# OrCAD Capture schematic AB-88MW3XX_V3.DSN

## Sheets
1 01 TITLE, TOC: title: AB-88MW3XX V3.0; rev: 1; note: MV-SRxxxxx-xx
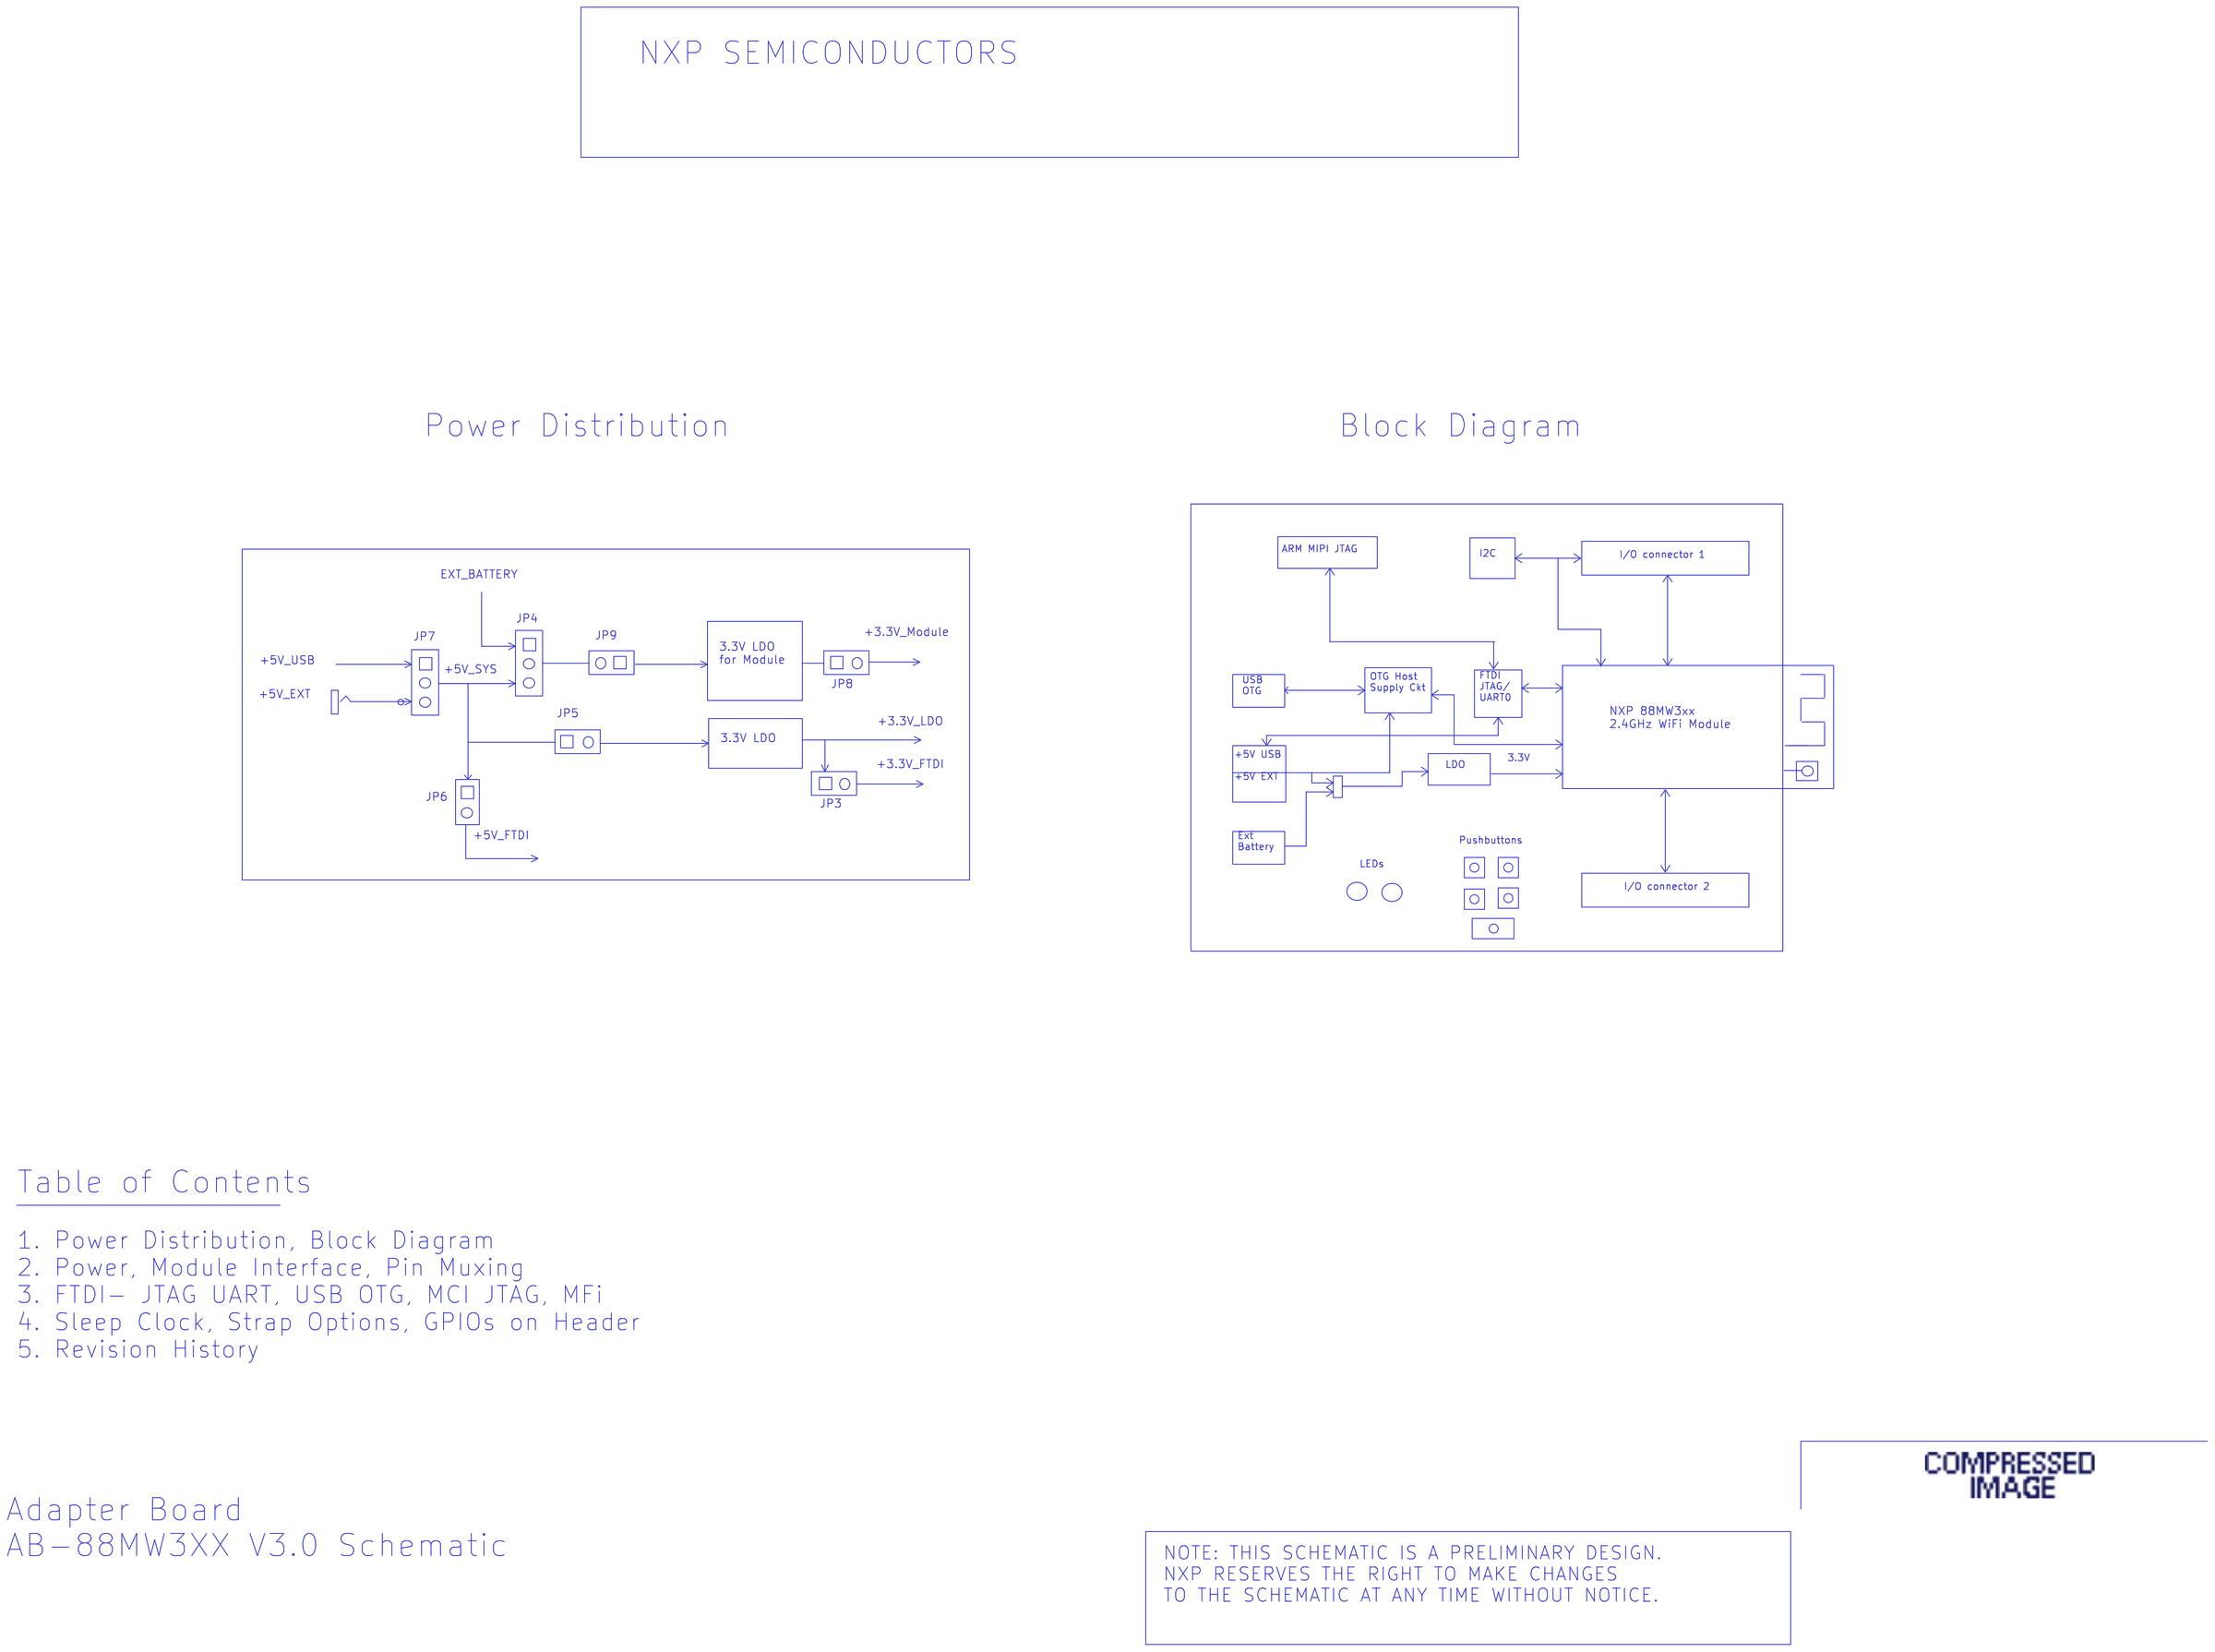
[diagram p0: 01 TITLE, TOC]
2 02 POWER, MODULE INTERFACE: size C
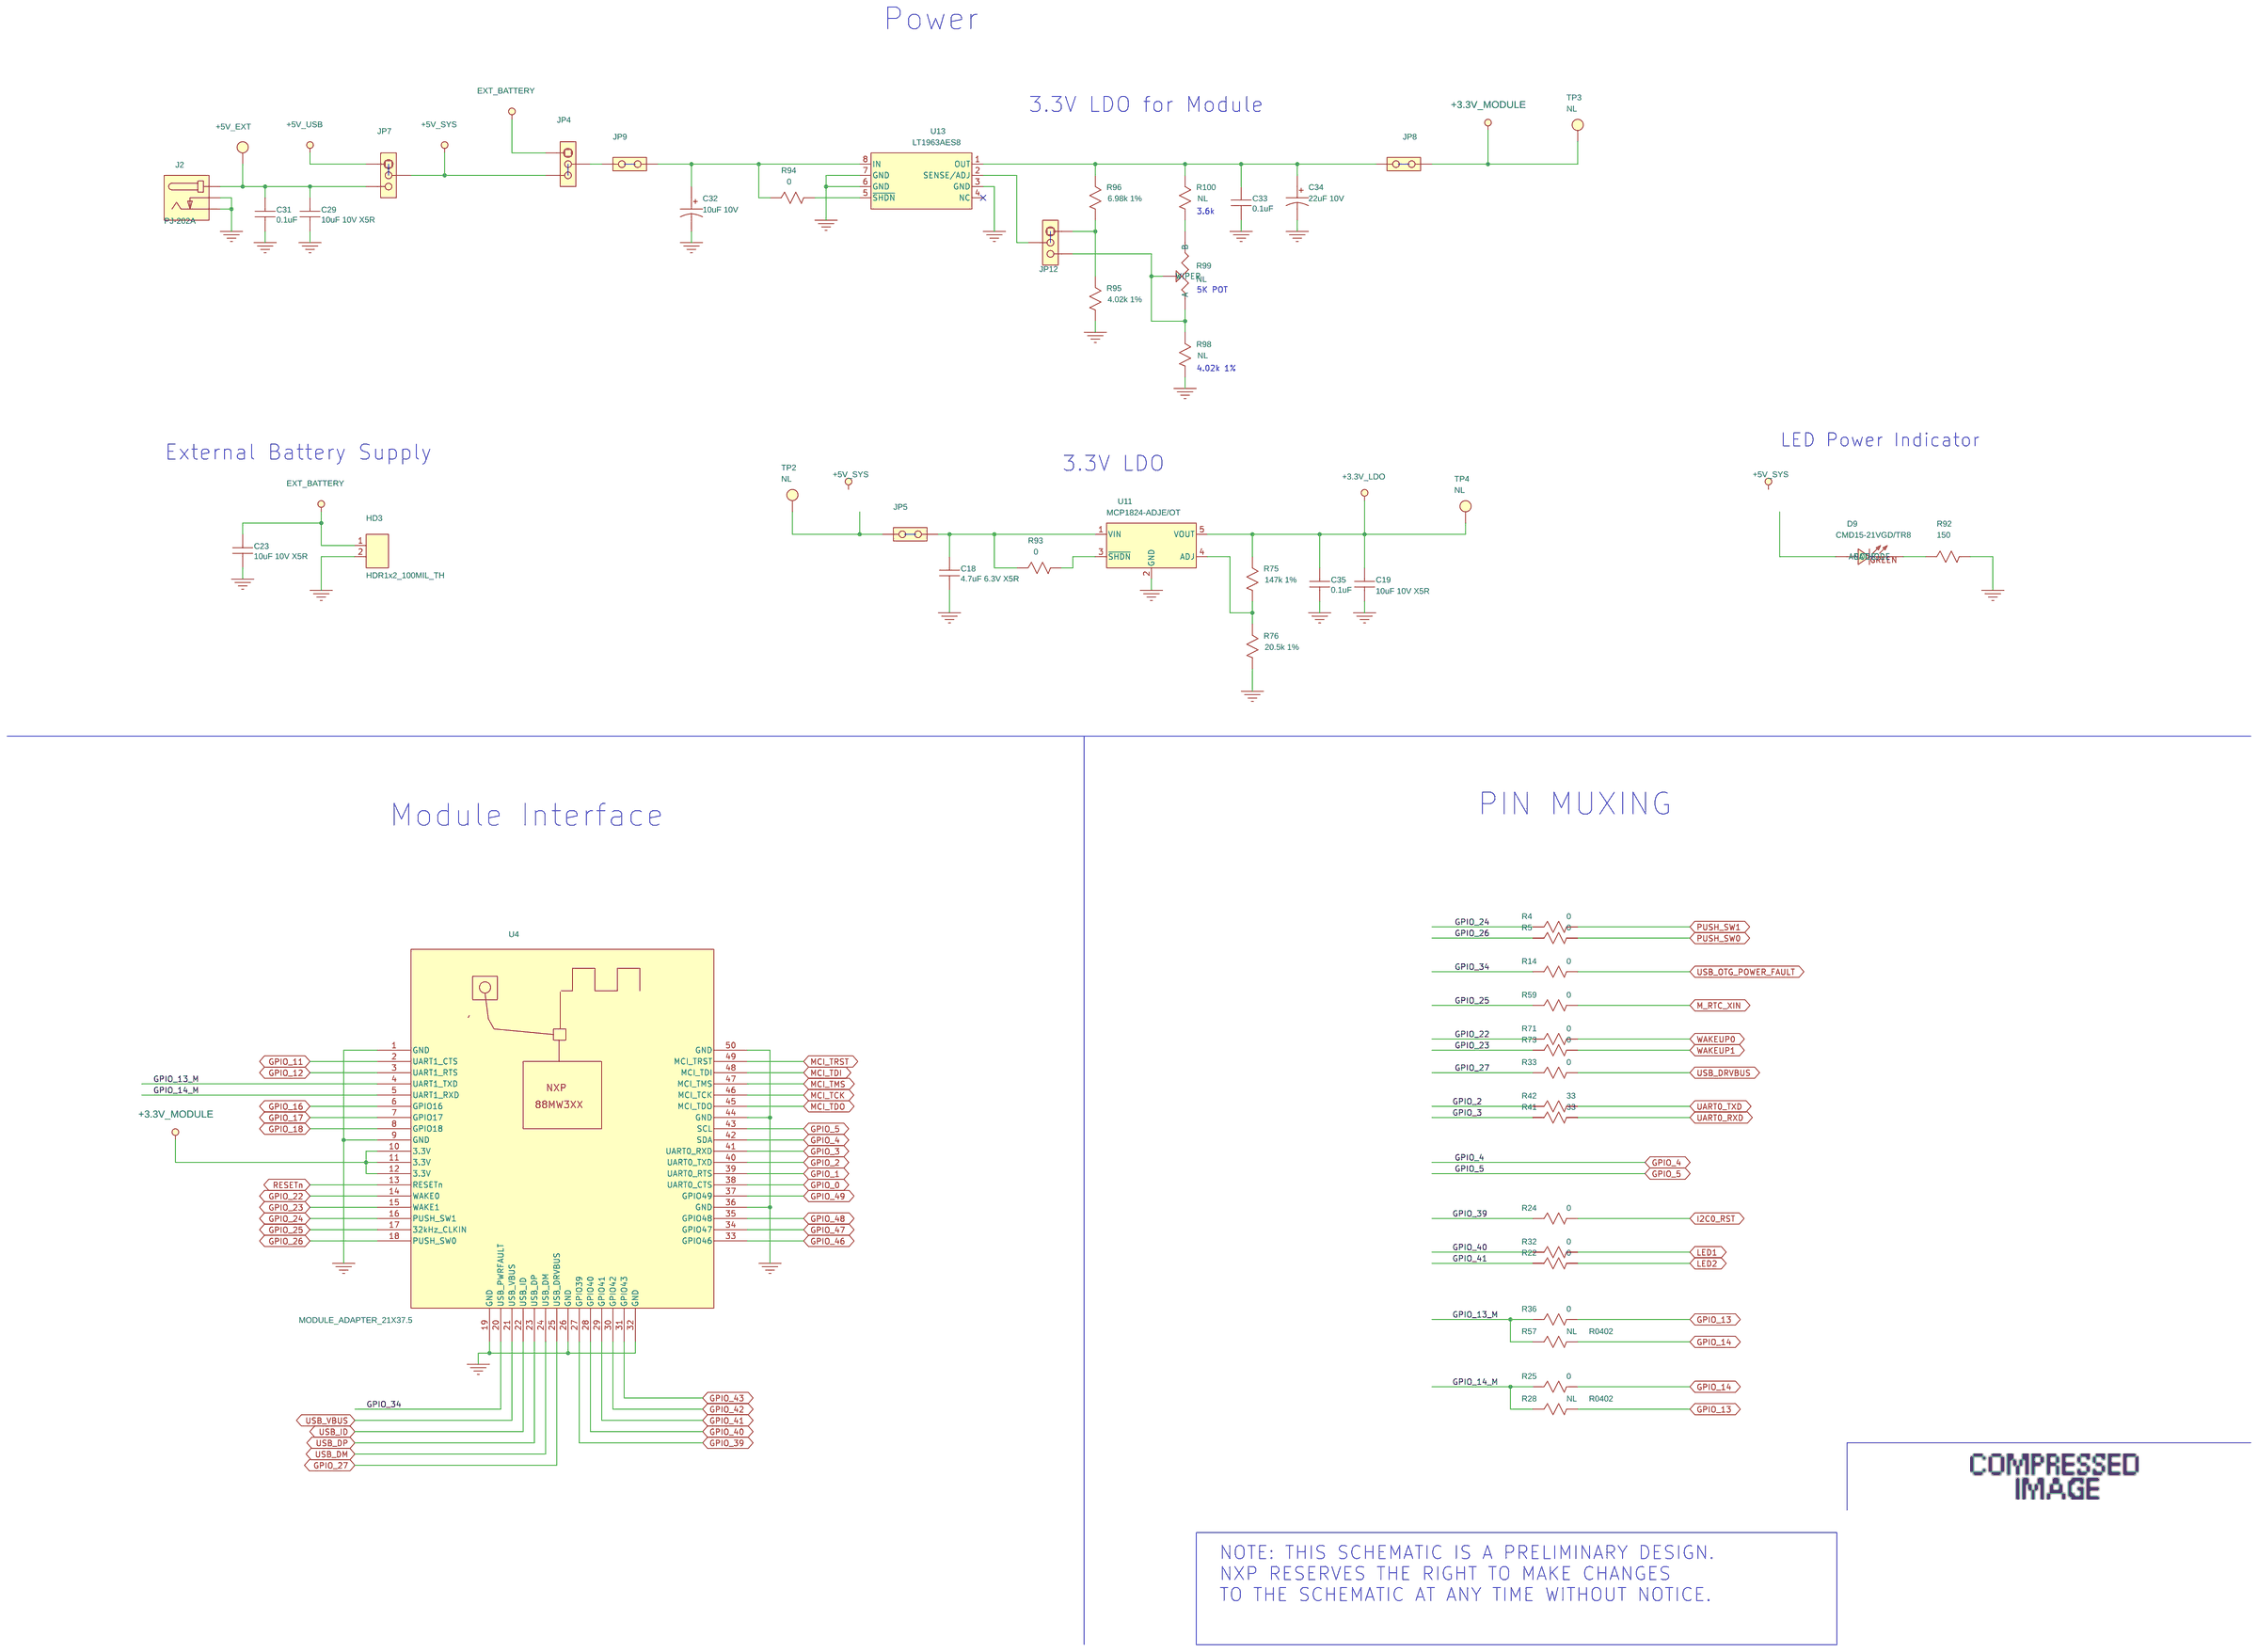
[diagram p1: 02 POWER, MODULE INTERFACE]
3 03 FTDI, USB OTG, I2C: size C
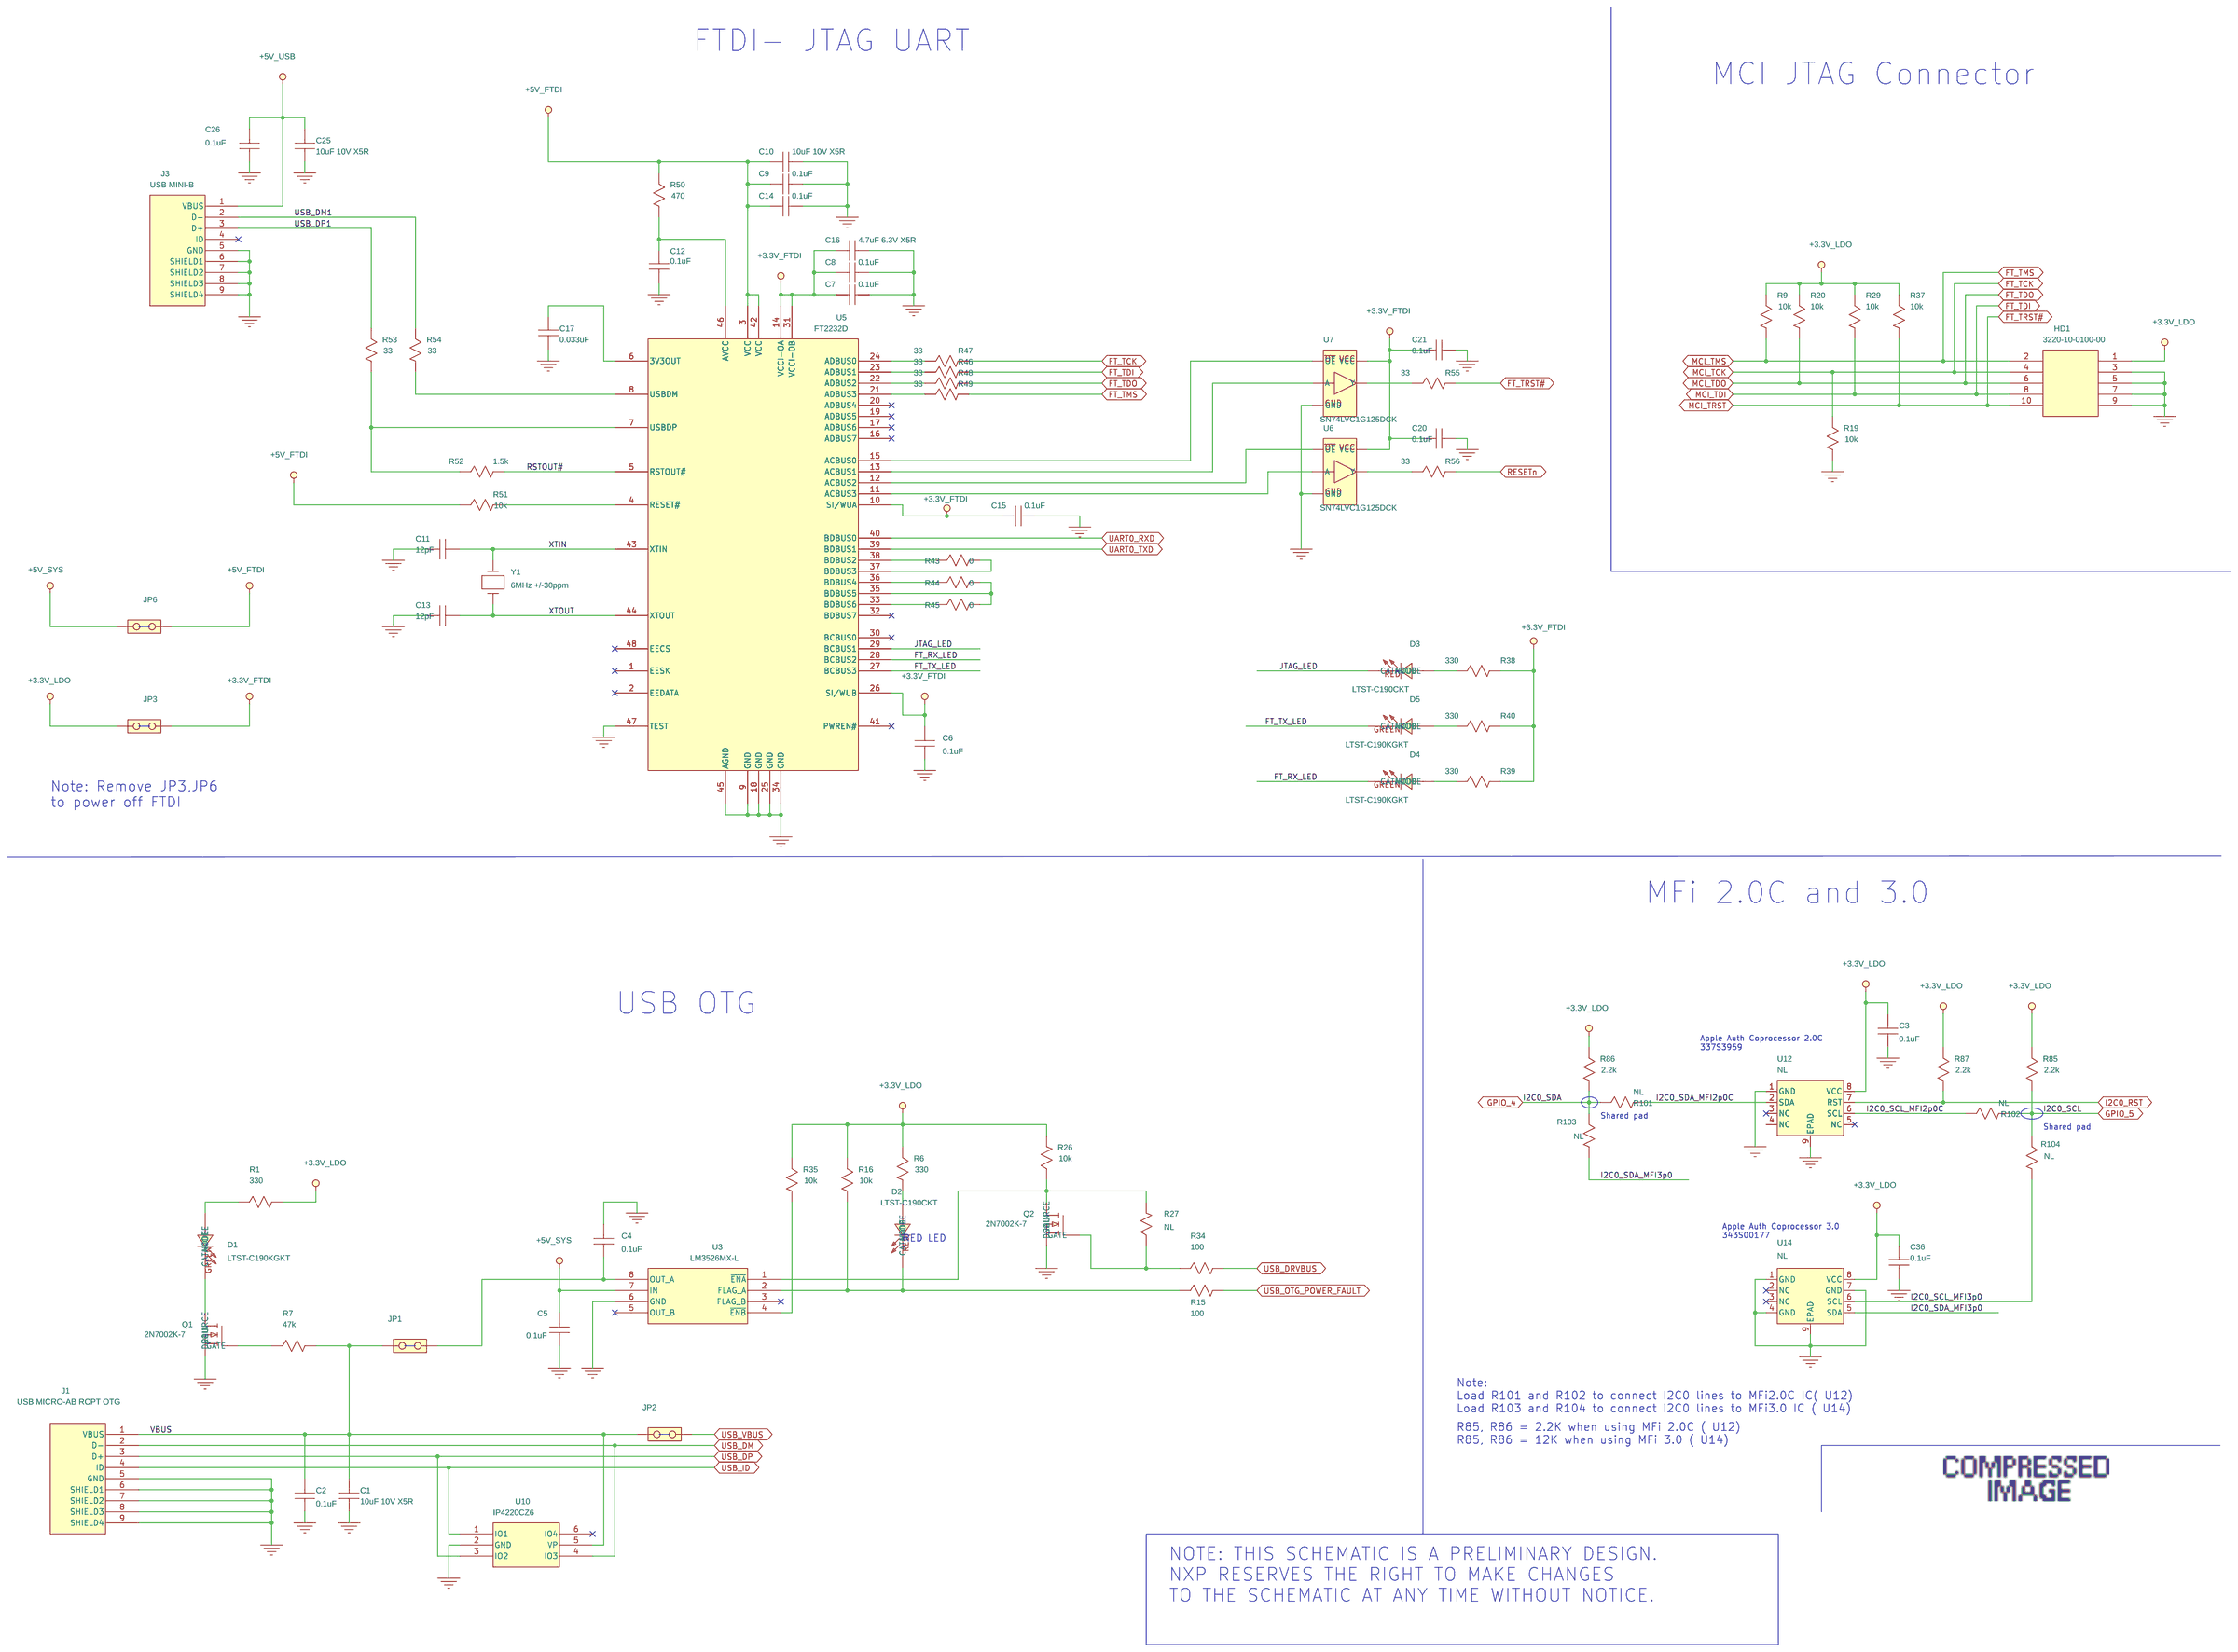
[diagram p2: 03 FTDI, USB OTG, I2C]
4 04 JTAG, IO connectors, LEDS: size C
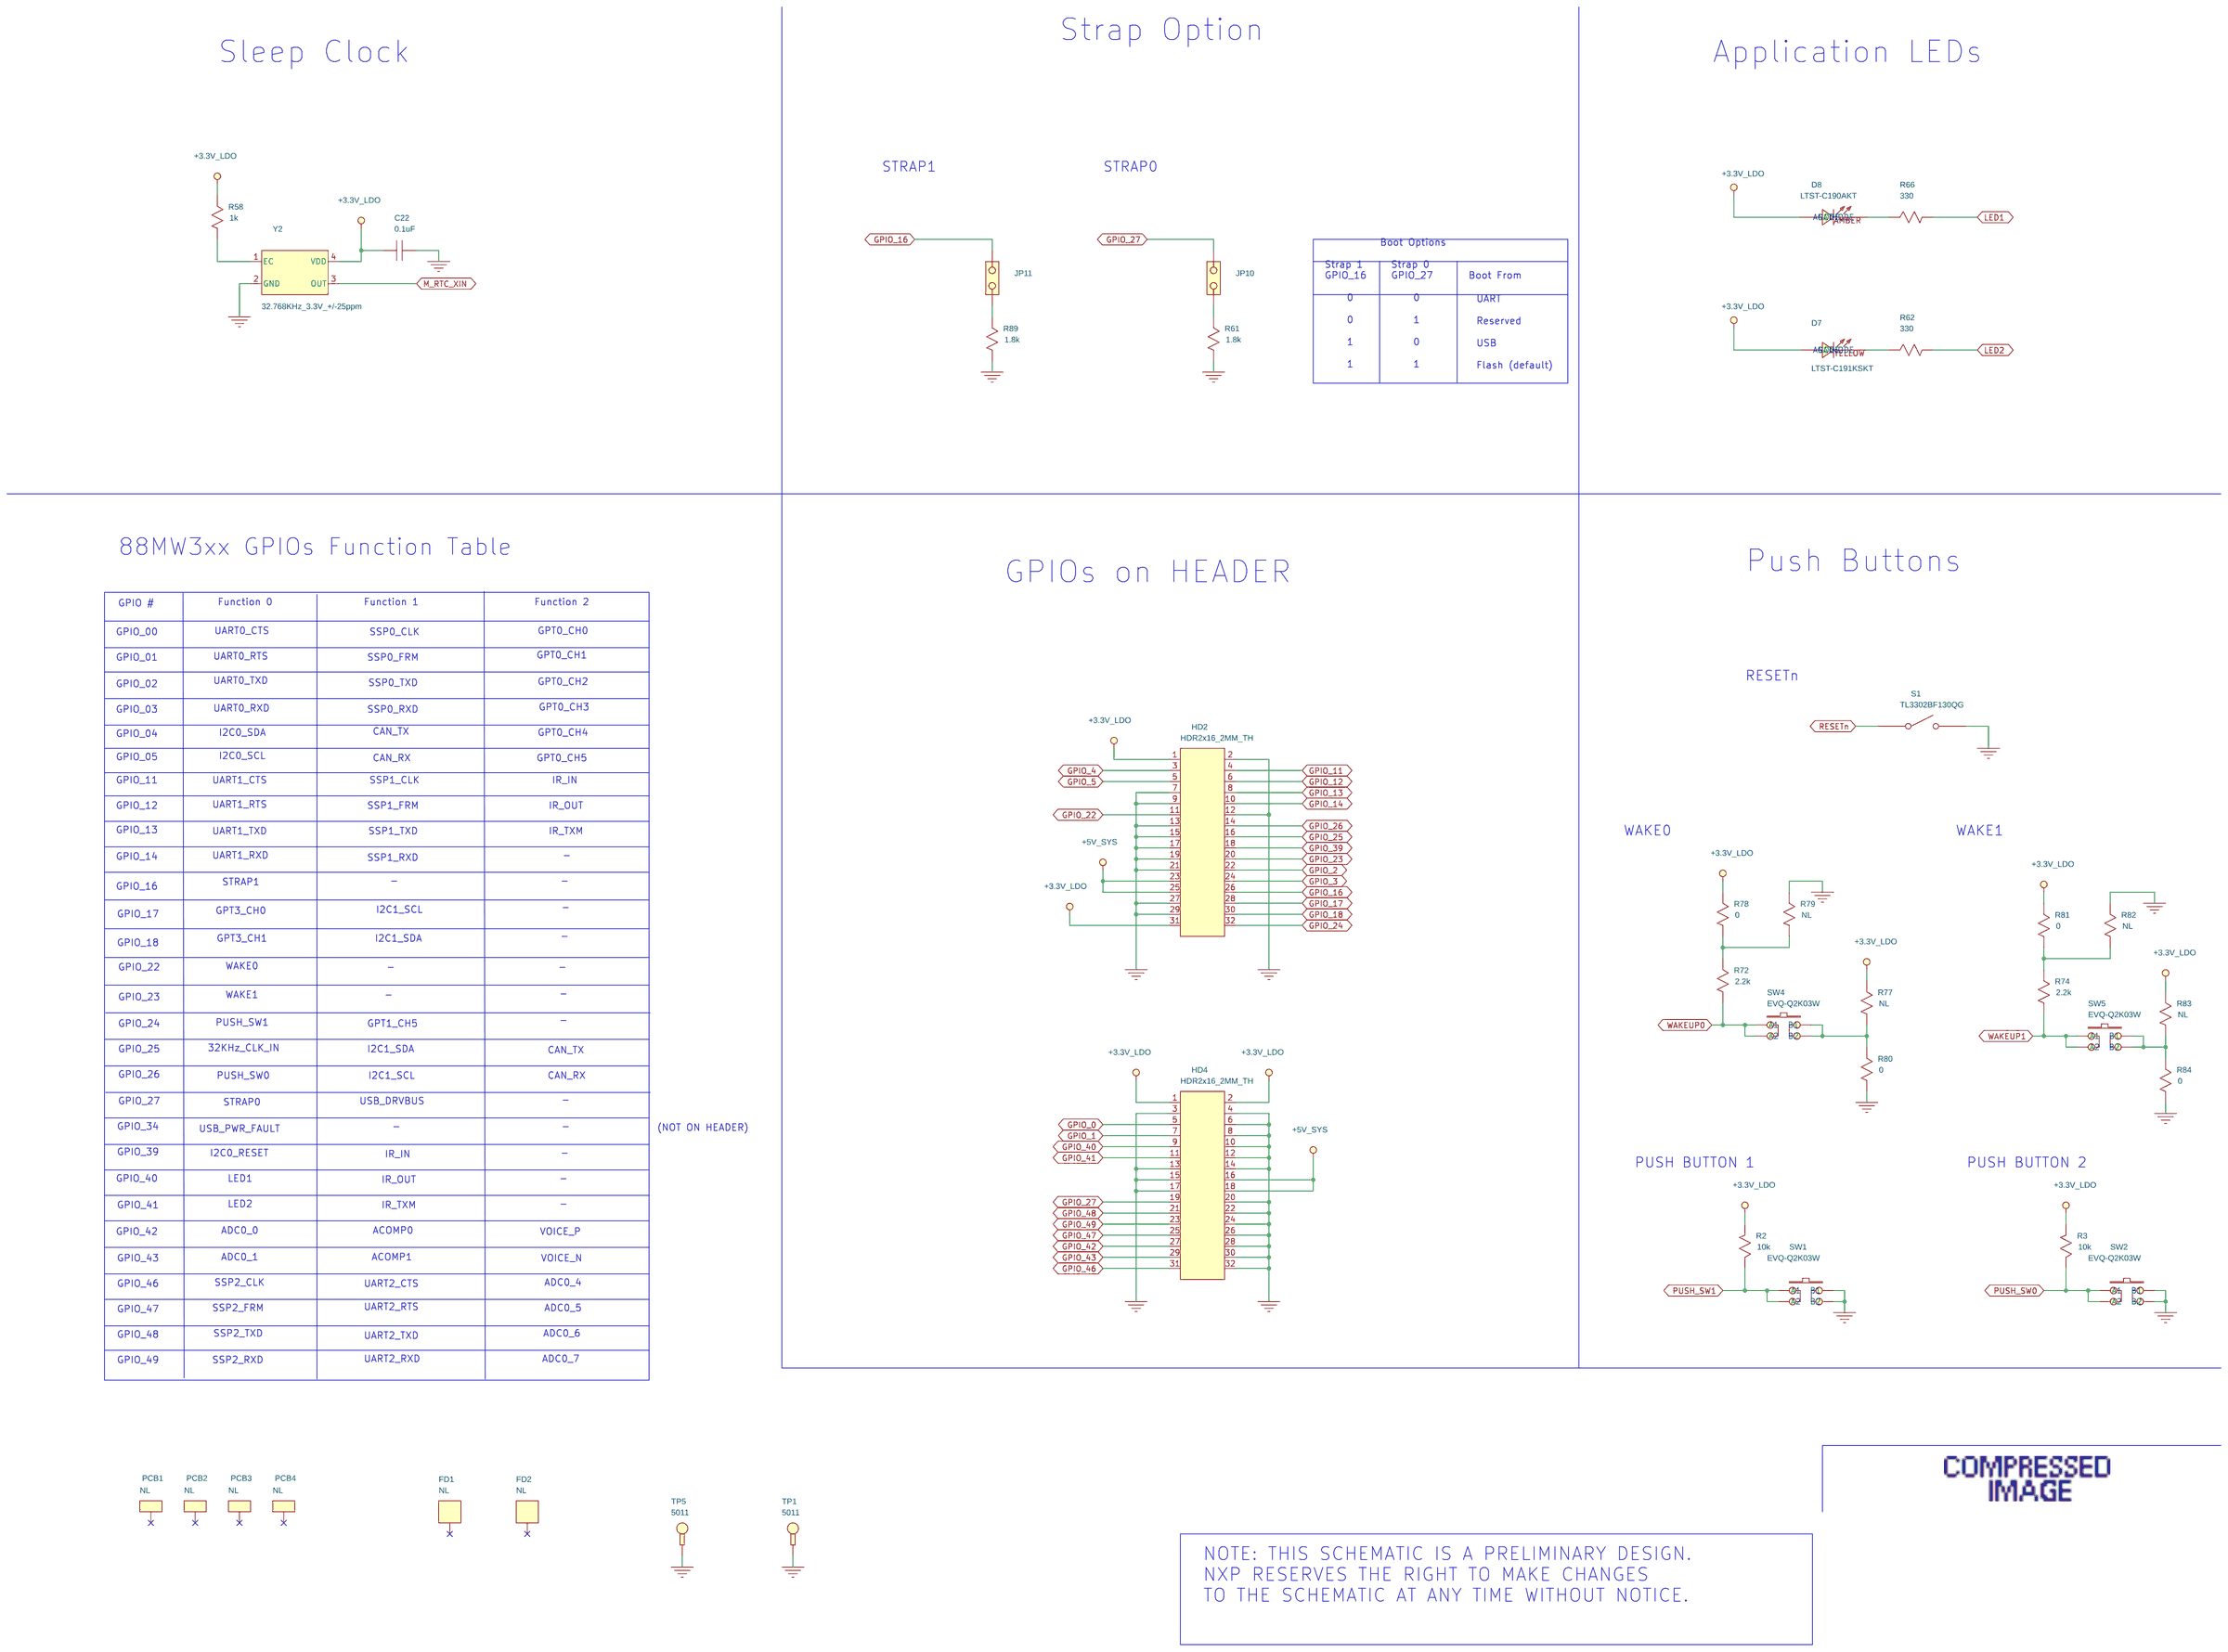
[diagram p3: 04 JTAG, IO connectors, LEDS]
5 05 REVISION HISTORY
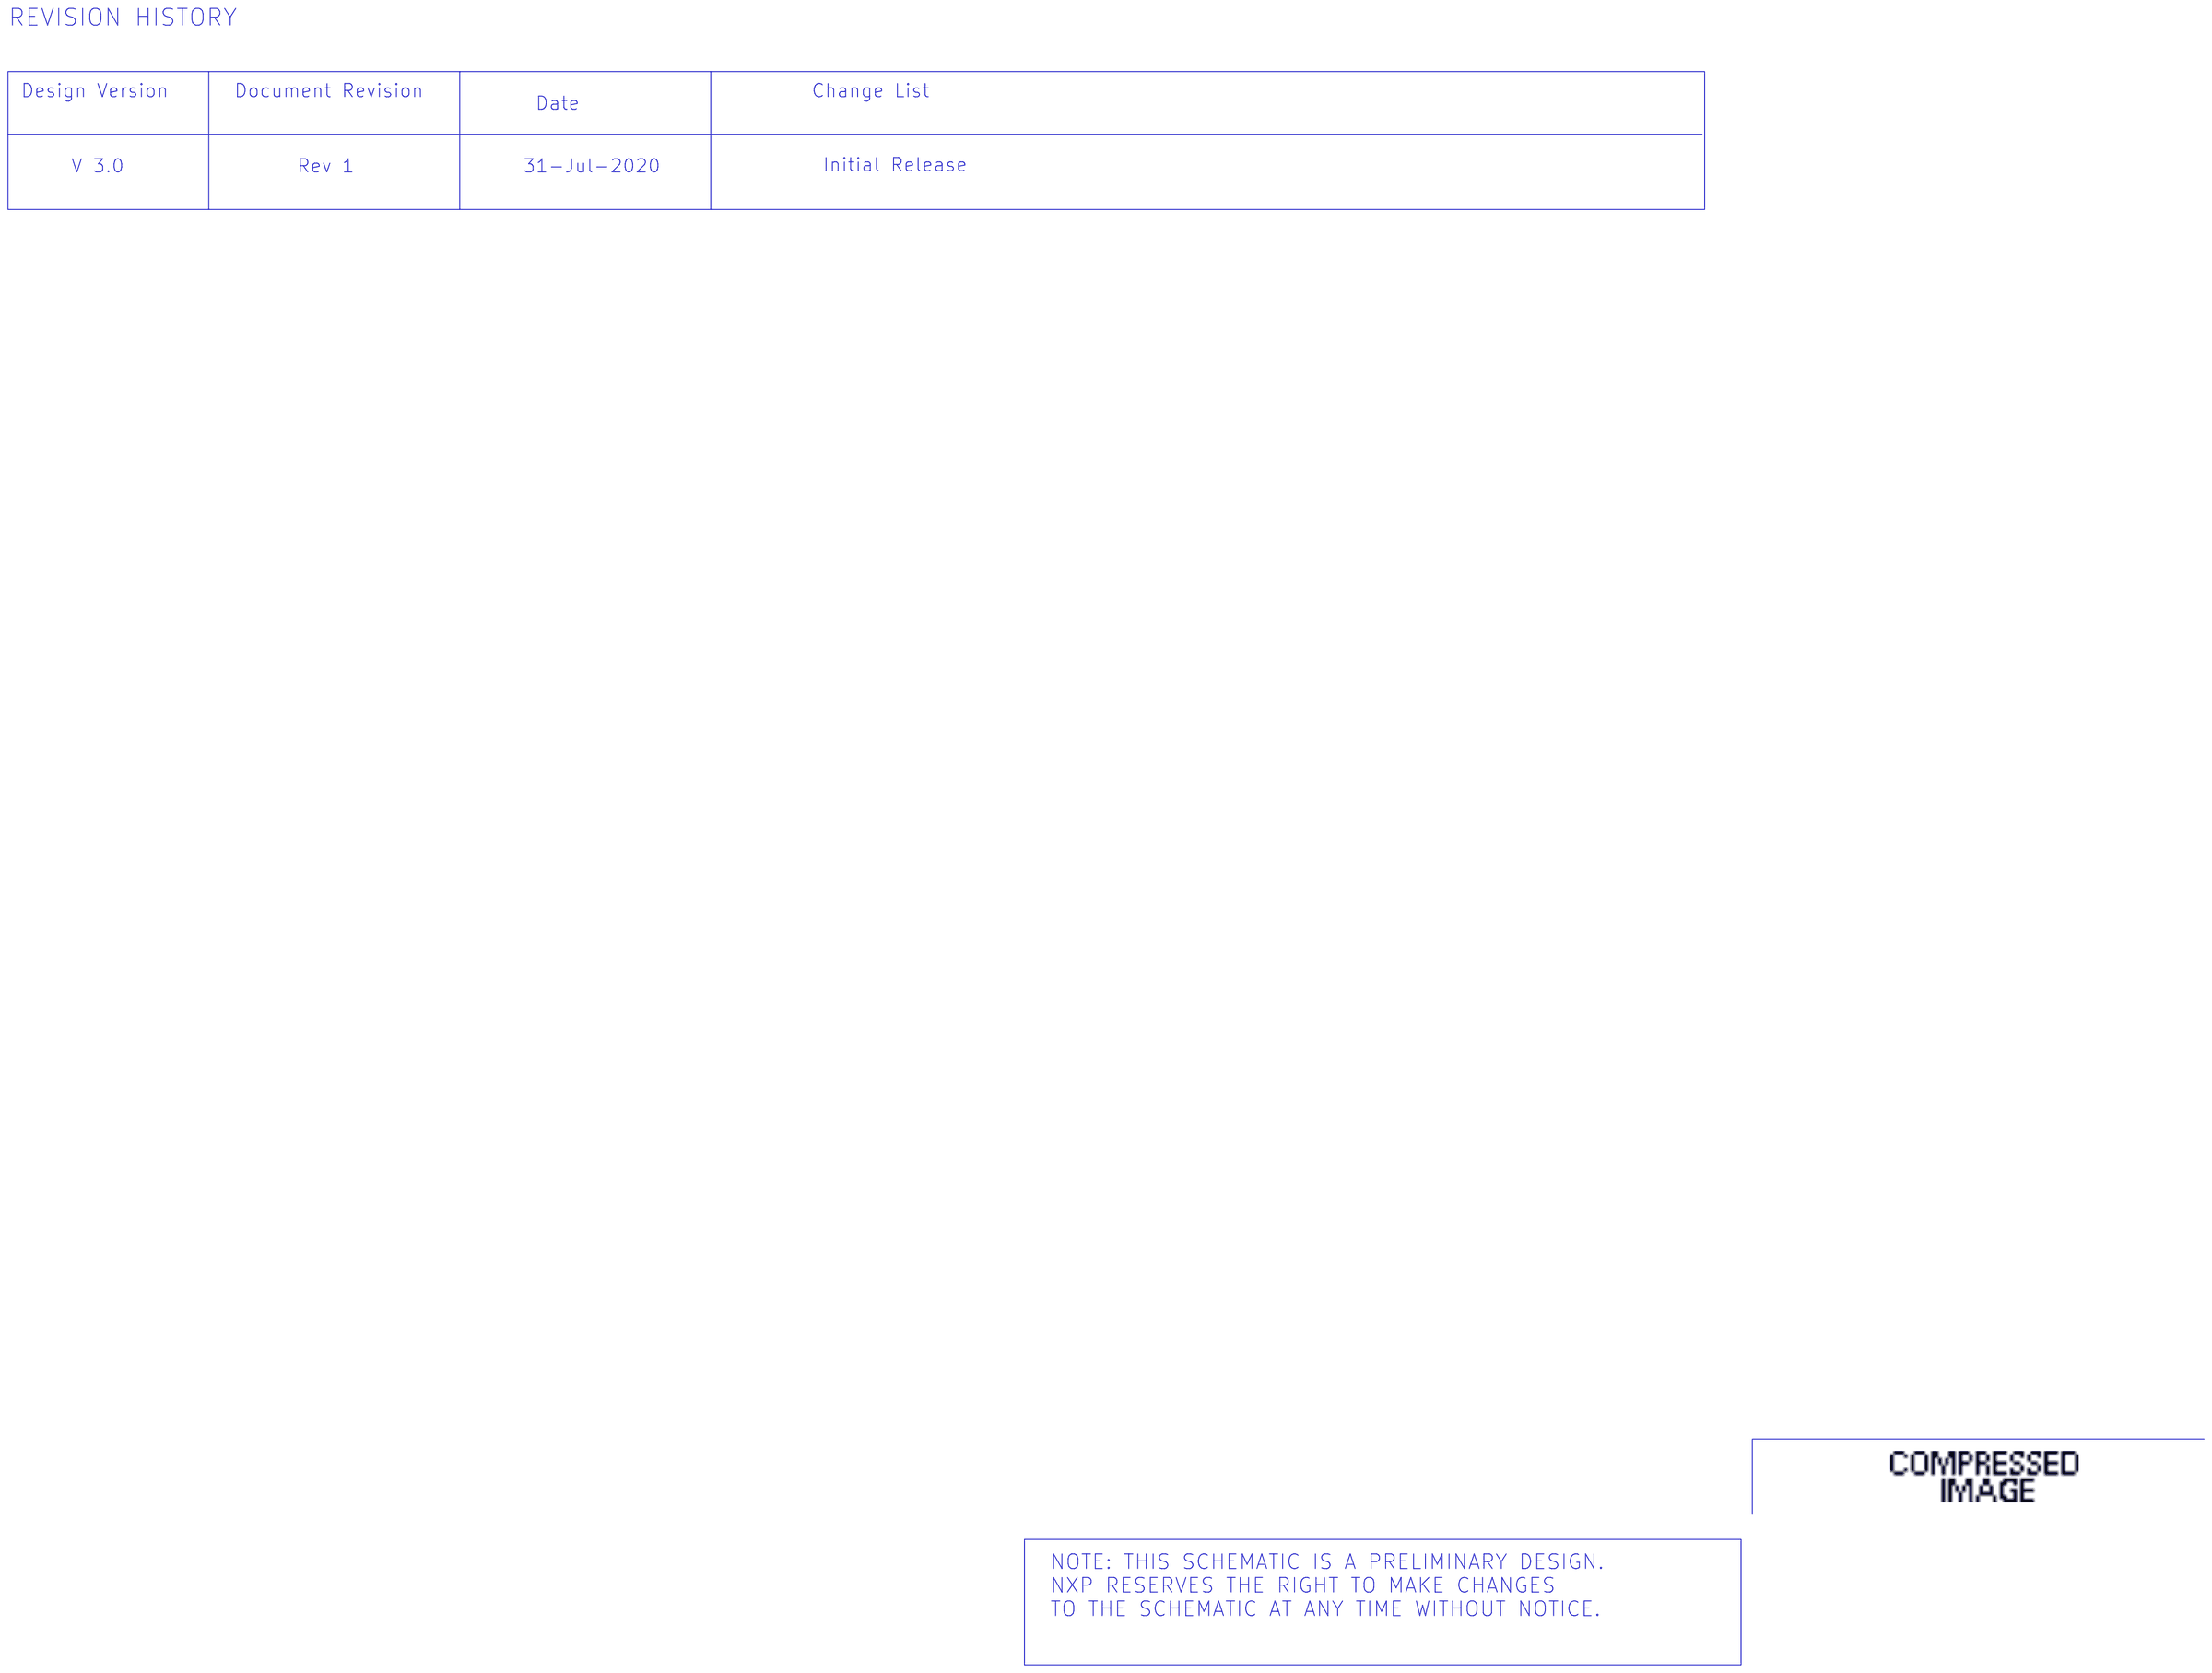
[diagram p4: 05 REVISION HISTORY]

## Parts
sheet 02 POWER, MODULE INTERFACE
C18  4.7uF 6.3V X5R  [C0603]
C19  10uF 10V X5R  [C0603]
C23  10uF 10V X5R  [C0603]
C29  10uF 10V X5R  [C0603]
C31  0.1uF  [C0402]
C32  10uF 10V  [ROHM_CAP_TANT_A-CASE]
C33  0.1uF  [C0402]
C34  22uF 10V  [ROHM_CAP_TANT_A-CASE]
C35  0.1uF  [C0402]
D9  CMD15-21VGD/TR8  [LED_CML_SMD_3.2X1.5]
HD3  HDR1x2_100MIL_TH  [HDR1X2_100MIL_TH2]
J2  PJ-202A  [CON_PWR_CUI_MALE2C3C_TH3_RA]
JP4  HDR1x3_100MIL_TH  [HDR1X3_100MIL_TH3]
JP5  HDR1x2_100MIL_TH  [HDR1X2_100MIL_TH2]
JP7  HDR1x3_100MIL_TH  [HDR1X3_100MIL_TH3]
JP8  HDR1x2_100MIL_TH  [HDR1X2_100MIL_TH2]
JP9  HDR1x2_100MIL_TH  [HDR1X2_100MIL_TH2]
JP12  HDR1x3_100MIL_TH  [HDR1X3_100MIL_TH3]
R4  0  [R0402]
R5  0  [R0402]
R14  0  [R0402]
R22  0  [R0402]
R24  0  [R0402]
R25  0  [R0402]
R28  NL  [R0402]
R32  0  [R0402]
R33  0  [R0402]
R36  0  [R0402]
R41  33  [R0402]
R42  33  [R0402]
R57  NL  [R0402]
R59  0  [R0402]
R71  0  [R0402]
R73  0  [R0402]
R75  147k 1%  [R0402]
R76  20.5k 1%  [R0402]
R92  150  [R0402]
R93  0  [R0402]
R94  0  [R0402]
R95  4.02k 1%  [R0402]
R96  6.98k 1%  [R0402]
R98  NL  [R0402]
R99  NL  [RES-POT_BRNS_VER_3314J]
R100  NL  [R0402]
TP2  NL  [TP_SMPAD30MIL]
TP3  NL  [TP_SMPAD30MIL]
TP4  NL  [TP_SMPAD30MIL]
U4  MODULE  [MODULE_ADAPTER_21X37.5]
U11  MCP1824-ADJE/OT  [IC_MCHP_SOT23-5]
U13  LT1963AES8  [IC_LLTC_SOIC8]
sheet 03 FTDI, USB OTG, I2C
C1  10uF 10V X5R  [C0603]
C2  0.1uF  [C0402]
C3  0.1uF  [C0402]
C4  0.1uF  [C0402]
C5  0.1uF  [C0402]
C6  0.1uF  [C0402]
C7  0.1uF  [C0402]
C8  0.1uF  [C0402]
C9  0.1uF  [C0402]
C10  10uF 10V X5R  [C0603]
C11  12pF  [C0402]
C12  0.1uF  [C0402]
C13  12pF  [C0402]
C14  0.1uF  [C0402]
C15  0.1uF  [C0402]
C16  4.7uF 6.3V X5R  [C0603]
C17  0.033uF  [C0402]
C20  0.1uF  [C0402]
C21  0.1uF  [C0402]
C25  10uF 10V X5R  [C0603]
C26  0.1uF  [C0402]
C36  0.1uF  [C0402]
D1  LTST-C190KGKT  [LED_LITE-ON_SMD_1.6X0.8]
D2  LTST-C190CKT  [LED_LITE-ON_SMD_1.6X0.8]
D3  LTST-C190CKT  [LED_LITE-ON_SMD_1.6X0.8]
D4  LTST-C190KGKT  [LED_LITE-ON_SMD_1.6X0.8]
D5  LTST-C190KGKT  [LED_LITE-ON_SMD_1.6X0.8]
HD1  3220-10-0100-00  [CON_HDR2X5_1.27MM_TH10_SHRD]
J1  USB MICRO-AB RCPT OTG  [USB-MICRO-AB_FCI_RCPT_SMD5_RA]
J3  USB MINI-B  [USB-MINI-B_MOLEX_54819x572]
JP1  HDR1x2_100MIL_TH  [HDR1X2_100MIL_TH2]
JP2  HDR1x2_100MIL_TH  [HDR1X2_100MIL_TH2]
JP3  HDR1x2_100MIL_TH  [HDR1X2_100MIL_TH2]
JP6  HDR1x2_100MIL_TH  [HDR1X2_100MIL_TH2]
Q1  2N7002K-7  [TRANS_DIOD_N-MFET_SOT23-3]
Q2  2N7002K-7  [TRANS_DIOD_N-MFET_SOT23-3]
R1  330  [R0402]
R6  330  [R0402]
R7  47k  [R0402]
R9  10k  [R0402]
R15  100  [R0402]
R16  10k  [R0402]
R19  10k  [R0402]
R20  10k  [R0402]
R26  10k  [R0402]
R27  NL  [R0402]
R29  10k  [R0402]
R34  100  [R0402]
R35  10k  [R0402]
R37  10k  [R0402]
R38  330  [R0402]
R39  330  [R0402]
R40  330  [R0402]
R43  0  [R0402]
R44  0  [R0402]
R45  0  [R0402]
R46  33  [R0402]
R47  33  [R0402]
R48  33  [R0402]
R49  33  [R0402]
R50  470  [R0402]
R51  10k  [R0402]
R52  1.5k  [R0402]
R53  33  [R0402]
R54  33  [R0402]
R55  33  [R0402]
R56  33  [R0402]
R85  2.2k  [R0402]
R86  2.2k  [R0402]
R87  2.2k  [R0402]
R101  NL  [R0402]
R102  NL  [R0402]
R103  NL  [R0402]
R104  NL  [R0402]
U3  LM3526MX-L  [IC_TI_SOIC8]
U5  FT2232D  [IC_FTDI_LQFP48L_7X7]
U6  SN74LVC1G125DCK  [IC_TI_SC70-5]
U7  SN74LVC1G125DCK  [IC_TI_SC70-5]
U10  IP4220CZ6  [IC_NXP_TSOP6]
U12  NL  [IC_IFX_PGUSON8-1_2.5X2.5]
U14  NL  [IC_APPLE_XDFN-8_3X2]
Y1  6MHz +/-30ppm  [XTAL_TXC_SMD2_12.5X4.8MM]
sheet 04 JTAG, IO connectors, LEDS
C22  0.1uF  [C0402]
D7  LTST-C191KSKT  [LED_LITE-ON_SMD_1.6X0.8]
D8  LTST-C190AKT  [LED_LITE-ON_SMD_1.6X0.8]
FD1  NL  [FIDUCIAL_40MP-80MM]
FD2  NL  [FIDUCIAL_40MP-80MM]
HD2  HDR2x16_2MM_TH  [HDR2X16_2MM_TH32]
HD4  HDR2x16_2MM_TH  [HDR2X16_2MM_TH32]
JP10  HDR1x2_100MIL_TH  [HDR1X2_100MIL_TH2]
JP11  HDR1x2_100MIL_TH  [HDR1X2_100MIL_TH2]
PCB1  NL  [MH_PTHDIA125MIL]
PCB2  NL  [MH_PTHDIA125MIL]
PCB3  NL  [MH_PTHDIA125MIL]
PCB4  NL  [MH_PTHDIA125MIL]
R2  10k  [R0402]
R3  10k  [R0402]
R58  1k  [R0402]
R61  1.8k  [R0402]
R62  330  [R0402]
R66  330  [R0402]
R72  2.2k  [R0402]
R74  2.2k  [R0402]
R77  NL  [R0402]
R78  0  [R0402]
R79  NL  [R0402]
R80  0  [R0402]
R81  0  [R0402]
R82  NL  [R0402]
R83  NL  [R0402]
R84  0  [R0402]
R89  1.8k  [R0402]
S1  TL3302BF130QG  [SW_ESW_TL3302BF_SMD2_10.2X3.5]
SW1  EVQ-Q2K03W  [SW_PAN_SMD4_6.5X6]
SW2  EVQ-Q2K03W  [SW_PAN_SMD4_6.5X6]
SW4  EVQ-Q2K03W  [SW_PAN_SMD4_6.5X6]
SW5  EVQ-Q2K03W  [SW_PAN_SMD4_6.5X6]
TP1  5011  [TP_KYST_TH1_90-63]
TP5  5011  [TP_KYST_TH1_90-63]
Y2  32.768KHz_3.3V_+/-25ppm  [XOSC_TXC_SMD_3.2X2.5MM]

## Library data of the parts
C16 C18 = CAP_NP: CAP CER 4.7uF 20% 6.3V X5R 0603 (0.8MM); Files: https://itapps.marvell.com/ACES/User/ServeFile.ashx?PartFileID=8; ManufacturerPn1: MURATA GRM188R60J475M; ManufacturerPn2: WALSIN 0603X475M6R3CT; ManufacturerPn3: TDK C1608X5R0J475M; Mfg1MrvlAvl: 0; Mfg2MrvlAvl: 0; Mfg3MrvlAvl: 0; Notes: 10% tol., higher voltage ok if not available; ObsoletedByPartID: 0; Part Number: 5044-001-001618; Part Type: CAP; PartType: CAP; Part_Number: 5044-001-001618; SourceLibrary: PARTS.OLB
C1 C10 C19 C23 C25 C29 = CAP_NP: CAP CER 10uF 10% 10V X5R 0603 (0.8MM); Files: https://itapps.marvell.com/ACES/User/ServeFile.ashx?PartFileID=8; ManufacturerPn1: TDK C1608X5R1A106K080AC; Mfg1MrvlAvl: 0; Mfg2MrvlAvl: 0; Mfg3MrvlAvl: 0; ObsoletedByPartID: 0; Part Number: 5044-001-002326; Part Type: CAP; PartType: CAP; Part_Number: 5044-001-002326; SourceLibrary: PARTS.OLB
C2-C9 C12 C14 C15 C20-C22 C26 C31 C33 C35 = CAP_NP: CAP CER 0.1uF 20% 16V X7R 0402 (0.5MM); Files: https://itapps.marvell.com/ACES/User/ServeFile.ashx?PartFileID=8; ManufacturerPn1: MURATA GRM155R71C104M; ManufacturerPn2: WALSIN 0402B104M160CT; ManufacturerPn3: TDK C1005X7R1C104M; Mfg1MrvlAvl: 0; Mfg2MrvlAvl: 0; Mfg3MrvlAvl: 0; ObsoletedByPartID: 0; Part Number: 5044-001-001608; Part Type: CAP; PartType: CAP; Part_Number: 5044-001-001608; SourceLibrary: PARTS.OLB
C32 = CAP_POL: CAP TANT 10UF 10V 20% 1206; Files: https://itapps.marvell.com/ACES/User/ServeFile.ashx?PartFileID=8; ManufacturerPn1: ROHM TCA1A106M8R; Mfg1MrvlAvl: 0; Mfg2MrvlAvl: 0; Mfg3MrvlAvl: 0; ObsoletedByPartID: 0; Part Number: 5044-001-002466; Part Type: CAP; PartType: CAP; Part_Number: 5044-001-002466; SourceLibrary: PARTS.OLB
C34 = CAP_POL: CAP TANT 22UF 10V 20% 1206; Files: https://itapps.marvell.com/ACES/User/ServeFile.ashx?PartFileID=8; ManufacturerPn1: ROHM TCA1A226M8R; Mfg1MrvlAvl: 0; Mfg2MrvlAvl: 0; Mfg3MrvlAvl: 0; ObsoletedByPartID: 0; Part Number: 5044-001-002467; Part Type: CAP; PartType: CAP; Part_Number: 5044-001-002467; SourceLibrary: PARTS.OLB
D9 = DIODE_LED_GREEN: LED GREEN DIFF SMD 3.2x1.5X1.1mm; Files: https://itapps.marvell.com/ACES/User/ServeFile.ashx?PartFileID=8; ManufacturerPn1: CML CMD15-21VGD/TR8; Mfg1MrvlAvl: 0; Mfg2MrvlAvl: 0; Mfg3MrvlAvl: 0; ObsoletedByPartID: 0; Part Number: 5044-001-002360; Part Type: PASSIVE; PartType: PASSIVE; Part_Number: 5044-001-002360; SourceLibrary: PARTS.OLB
HD3 = HDR1X2_100MIL_v2: HDR 1x2 MALE 0.025in SQ PINS, 100MIL TH; Files: https://itapps.marvell.com/ACES/User/ServeFile.ashx?PartFileID=8; ManufacturerPn1: Samtec TSW-102-07-G-S; Mfg1MrvlAvl: 0; Mfg2MrvlAvl: 0; Mfg3MrvlAvl: 0; ObsoletedByPartID: 0; Part Number: 5044-001-001841; Part Type: CONN; PartType: CONN; Part_Number: 5044-001-001841; SourceLibrary: PARTS.OLB
J2 = CON_PWR_JACK: CONN PWR JACK 16VDC @2.5A MALE 2MM CENTER-PIN 3MM TH-TAB RA TH; Files: https://itapps.marvell.com/ACES/User/ServeFile.ashx?PartFileID=8; ManufacturerPn1: CUI PJ-202A; Mfg1MrvlAvl: 0; Mfg2MrvlAvl: 0; Mfg3MrvlAvl: 0; ObsoletedByPartID: 0; Part Number: 5044-001-002015; Part Type: CONN; PartType: CONN; Part_Number: 5044-001-002015; SourceLibrary: PARTS.OLB
JP4 JP7 JP12 = HDR1X3_100MIL: HDR 1x3 MALE 0.025in SQ PINS, 100MIL TH; Files: https://itapps.marvell.com/ACES/User/ServeFile.ashx?PartFileID=8; ManufacturerPn1: Samtec TSW-103-07-G-S; Mfg1MrvlAvl: 0; Mfg2MrvlAvl: 0; Mfg3MrvlAvl: 0; ObsoletedByPartID: 0; Part Number: 5044-001-001842; Part Type: CONN; PartType: CONN; Part_Number: 5044-001-001842; SourceLibrary: PARTS.OLB
JP1-JP3 JP5 JP6 JP8-JP11 = HDR1X2_100MIL: HDR 1x2 MALE 0.025in SQ PINS, 100MIL TH; Files: https://itapps.marvell.com/ACES/User/ServeFile.ashx?PartFileID=8; ManufacturerPn1: Samtec TSW-102-07-G-S; Mfg1MrvlAvl: 0; Mfg2MrvlAvl: 0; Mfg3MrvlAvl: 0; ObsoletedByPartID: 0; Part Number: 5044-001-001841; Part Type: CONN; PartType: CONN; Part_Number: 5044-001-001841; SourceLibrary: PARTS.OLB
R4 R5 R14 R22 R24 R25 R32 R33 R36 R43-R45 R59 R71 R73 R78 R80 R81 R84 R93 R94 = RES: RES THICK FILM 0 OHM 1/16W 5% 0402 SMD; Files: https://itapps.marvell.com/ACES/User/ServeFile.ashx?PartFileID=8; ManufacturerPn1: Cyntec PFR05S-000-XNH; ManufacturerPn2: Walsin WR04X000 PTL; ManufacturerPn3: Yageo RC0402JR-070RL; OneKkPerMoPriceTarget: 0.00020; Part Number: 5044-001-001293; Part_Number: 5044-001-001293; ProtoPriceTargetPerUnit: 0.00150; SourceLibrary: PARTS.OLB
R27 R28 R57 R79 R82 = RES: RES THICK FILM 0 OHM 1/16W 5% 0402 SMD; Files: https://itapps.marvell.com/ACES/User/ServeFile.ashx?PartFileID=8; ManufacturerPn1: Cyntec PFR05S-000-XNH; ManufacturerPn2: Walsin WR04X000 PTL; ManufacturerPn3: Yageo RC0402JR-070RL; Mfg1MrvlAvl: 0; Mfg2MrvlAvl: 0; Mfg3MrvlAvl: 0; ObsoletedByPartID: 0; OneHundredKPerMoPriceTarget: 0; OneKkPerMoPriceTarget: 0; Part_Number: 5044-001-001293; ProtoPriceTargetPerUnit: 0; SourceLibrary: PARTS.OLB
R41 R42 R46-R49 R53-R56 = RES: RES THICK FILM 33 OHM 1/16W 5%  0402 SMD; Files: https://itapps.marvell.com/ACES/User/ServeFile.ashx?PartFileID=8; ManufacturerPn1: Cyntec PFR05S-330-JNH; ManufacturerPn2: Walsin WR04X330 JTL; ManufacturerPn3: Yageo RC0402JR-0733RL; Mfg1MrvlAvl: 0; Mfg2MrvlAvl: 0; Mfg3MrvlAvl: 0; ObsoletedByPartID: 0; OneKkPerMoPriceTarget: 0.00020; Part Number: 5044-001-001330; Part_Number: 5044-001-001330; ProtoPriceTargetPerUnit: 0.00150; SourceLibrary: PARTS.OLB
R75 = RES: RES THICK FILM 147K OHM 1/16W 1% 0402 SMD; Files: https://itapps.marvell.com/ACES/User/ServeFile.ashx?PartFileID=8; ManufacturerPn1: Cyntec PFR05S-1473-FNH; ManufacturerPn2: Walsin WR04X1473FTL; ManufacturerPn3: Yageo RC0402FR-07147KL; Mfg1MrvlAvl: 0; Mfg2MrvlAvl: 0; Mfg3MrvlAvl: 0; ObsoletedByPartID: 0; OneKkPerMoPriceTarget: 0.00030; Part Number: 5044-001-001120; Part_Number: 5044-001-001120; ProtoPriceTargetPerUnit: 0.00200; SourceLibrary: PARTS.OLB
R76 = RES: RES THICK FILM 20.5K OHM 1/16W 1% 0402 SMD; Files: https://itapps.marvell.com/ACES/User/ServeFile.ashx?PartFileID=8; ManufacturerPn1: Cyntec PFR05S-2052-FNH; ManufacturerPn2: Walsin WR04X2052FTL; ManufacturerPn3: Yageo RC0402FR-0720K5L; Mfg1MrvlAvl: 0; Mfg2MrvlAvl: 0; Mfg3MrvlAvl: 0; ObsoletedByPartID: 0; OneKkPerMoPriceTarget: 0.00030; Part Number: 5044-001-001042; Part_Number: 5044-001-001042; ProtoPriceTargetPerUnit: 0.00200; SourceLibrary: PARTS.OLB
R92 = RES: RES THICK FILM 150 OHM 1/16W 5%  0402 SMD; Files: https://itapps.marvell.com/ACES/User/ServeFile.ashx?PartFileID=8; ManufacturerPn1: Cyntec PFR05S-151-JNH; ManufacturerPn2: Walsin WR04X151 JTL; ManufacturerPn3: Yageo RC0402JR-07150RL; Mfg1MrvlAvl: 0; Mfg2MrvlAvl: 0; Mfg3MrvlAvl: 0; ObsoletedByPartID: 0; OneKkPerMoPriceTarget: 0.00020; Part Number: 5044-001-001346; Part_Number: 5044-001-001346; ProtoPriceTargetPerUnit: 0.00150; SourceLibrary: PARTS.OLB
R95 R98 = RES: RES THICK FILM 4.02K OHM 1/16W 1% 0402 SMD; Files: https://itapps.marvell.com/ACES/User/ServeFile.ashx?PartFileID=8; ManufacturerPn1: Cyntec PFR05S-4021-FNH; ManufacturerPn2: Walsin WR04X4021FTL; ManufacturerPn3: Yageo RC0402FR-074K02L; Mfg1MrvlAvl: 0; Mfg2MrvlAvl: 0; Mfg3MrvlAvl: 0; ObsoletedByPartID: 0; OneKkPerMoPriceTarget: 0.00030; Part Number: 5044-001-000980; Part_Number: 5044-001-000980; ProtoPriceTargetPerUnit: 0.00200; SourceLibrary: PARTS.OLB
R96 = RES: RES THICK FILM 6.98K OHM 1/16W 1% 0402 SMD; Files: https://itapps.marvell.com/ACES/User/ServeFile.ashx?PartFileID=8; ManufacturerPn1: Cyntec PFR05S-6981-FNH; ManufacturerPn2: Walsin WR04X6981FTL; ManufacturerPn3: Yageo RC0402FR-076K98L; Mfg1MrvlAvl: 0; Mfg2MrvlAvl: 0; Mfg3MrvlAvl: 0; ObsoletedByPartID: 0; OneKkPerMoPriceTarget: 0.00030; Part Number: 5044-001-001003; Part_Number: 5044-001-001003; ProtoPriceTargetPerUnit: 0.00200; SourceLibrary: PARTS.OLB
R99 = RES_POT: RES TRIMPOT 5K OHM 0.25W TOP ADJ VER SMD 4.5x4.5x2.55mm; Files: https://itapps.marvell.com/ACES/User/ServeFile.ashx?PartFileID=8; ManufacturerPn1: BOURNS 3314J-1-502E; Mfg1MrvlAvl: 0; Mfg2MrvlAvl: 0; Mfg3MrvlAvl: 0; ObsoletedByPartID: 0; Part Number: 5044-001-002408; Part Type: RES; PartType: RES; Part_Number: 5044-001-002408; SourceLibrary: PARTS.OLB
R100 = RES: RES THICK FILM 3.6K OHM 1/16W 5%  0402 SMD; Files: https://itapps.marvell.com/ACES/User/ServeFile.ashx?PartFileID=8; ManufacturerPn1: Cyntec PFR05S-362-JNH; ManufacturerPn2: Walsin WR04X362 JTL; ManufacturerPn3: Yageo RC0402JR-073K6L; Mfg1MrvlAvl: 0; Mfg2MrvlAvl: 0; Mfg3MrvlAvl: 0; ObsoletedByPartID: 0; OneKkPerMoPriceTarget: 0.00020; Part Number: 5044-001-001379; Part_Number: 5044-001-001379; ProtoPriceTargetPerUnit: 0.00150; SourceLibrary: PARTS.OLB
TP2-TP4 = TESTPOINT: MRVL SMD TESTPOINT SIZE 30 MIL; Files: https://itapps.marvell.com/ACES/User/ServeFile.ashx?PartFileID=8; ManufacturerPn1: MRVL TP30MIL; Mfg1MrvlAvl: 0; Mfg2MrvlAvl: 0; Mfg3MrvlAvl: 0; ObsoletedByPartID: 0; OneHundredKPerMoPriceTarget: 0; OneKkPerMoPriceTarget: 0; PartType: PCB; Part_Number: TP30MIL; ProtoPriceTargetPerUnit: 0; SourceLibrary: PARTS.OLB
U4 = MODULE_8
U11 = IC_LDO_MCHP_MCP1824-ADJ_SOT23: IC REG LDO LV 300MA ADJ  SOT23-5; Files: https://itapps.marvell.com/ACES/User/ServeFile.ashx?PartFileID=8; ManufacturerPn1: MicroChip MCP1824T-ADJE/OT; Mfg1MrvlAvl: 0; Mfg2MrvlAvl: 0; Mfg3MrvlAvl: 0; ObsoletedByPartID: 0; Part Number: 5044-001-001961; Part Type: IC; PartType: IC; Part_Number: 5044-001-001961; SourceLibrary: PARTS.OLB
U13 = IC_LDO_LLTC_LT1963A-ADJ_SOIC8: IC REG LDO 1.5A ADJ SOIC-8; Files: https://itapps.marvell.com/ACES/User/ServeFile.ashx?PartFileID=8; ManufacturerPn1: Linear-Tech LT1963AES8; Mfg1MrvlAvl: 0; Mfg2MrvlAvl: 0; Mfg3MrvlAvl: 0; ObsoletedByPartID: 0; Part Number: 5044-001-001958; Part Type: IC; PartType: IC; Part_Number: 5044-001-001958; SourceLibrary: PARTS.OLB
C11 C13 = CAP_NP: CAP CER 12pF 5% 50V C0G 0402 (0.5MM); Files: https://itapps.marvell.com/ACES/User/ServeFile.ashx?PartFileID=8; ManufacturerPn1: MURATA GRM1555C1H120J; ManufacturerPn2: WALSIN 0402N120J500LT; ManufacturerPn3: TDK C1005C0G1H120J; Mfg1MrvlAvl: 0; Mfg2MrvlAvl: 0; Mfg3MrvlAvl: 0; ObsoletedByPartID: 0; OneKkPerMoPriceTarget: 0.00060; Part Number: 5044-001-001573; Part Type: CAP; PartType: CAP; Part_Number: 5044-001-001573; SourceLibrary: PARTS.OLB
C17 = CAP_NP: CAP CER 0.033uF 10% 25V X7R 0402 (0.5MM); Files: https://itapps.marvell.com/ACES/User/ServeFile.ashx?PartFileID=8; ManufacturerPn1: MURATA GRM155R71E333K; ManufacturerPn2: TDK C1005X7R1E333K; Mfg1MrvlAvl: 0; Mfg2MrvlAvl: 0; Mfg3MrvlAvl: 0; ObsoletedByPartID: 0; Part Number: 5044-001-001605; Part Type: CAP; PartType: CAP; Part_Number: 5044-001-001605; SourceLibrary: PARTS.OLB
C36 = CAP_NP: CAP CER 0.1uF 20% 16V X7R 0402 (0.5MM); ManufacturerPn1: MURATA GRM155R71C104M; ManufacturerPn2: WALSIN 0402B104M160CT; ManufacturerPn3: TDK C1005X7R1C104M; Mfg1MrvlAvl: 0; Mfg2MrvlAvl: 0; Mfg3MrvlAvl: 0; ObsoletedByPartID: 0; Part Number: 5044-001-001608; Part Type: CAP; SourceLibrary: PARTS.OLB
D1 = DIODE_LED_GREEN: LED GREEN CLEAR SMD 1.6x0.8x0.8mm; Files: https://itapps.marvell.com/ACES/User/ServeFile.ashx?PartFileID=8; ManufacturerPn1: LITE-ON LTST-C190KGKT; Mfg1MrvlAvl: 0; Mfg2MrvlAvl: 0; Mfg3MrvlAvl: 0; ObsoletedByPartID: 0; Part Number: 5044-001-002280; Part Type: PASSIVE; PartType: PASSIVE; Part_Number: 5044-001-002280; SourceLibrary: PARTS.OLB
D2 D3 = DIODE_LED_RED: LED RED CLEAR SMD 1.6x0.8x0.8mm; ManufacturerPn1: LITE-ON LTST-C190CKT; Mfg1MrvlAvl: 0; Mfg2MrvlAvl: 0; Mfg3MrvlAvl: 0; ObsoletedByPartID: 0; Part Number: 5044-001-002258; Part Type: PASSIVE; SourceLibrary: PARTS.OLB
D4 D5 = DIODE_LED_GREEN: LED GREEN CLEAR SMD 1.6x0.8x0.8mm; ManufacturerPn1: LITE-ON LTST-C190KGKT; Mfg1MrvlAvl: 0; Mfg2MrvlAvl: 0; Mfg3MrvlAvl: 0; ObsoletedByPartID: 0; Part Number: 5044-001-002280; Part Type: PASSIVE; SourceLibrary: PARTS.OLB
HD1 = CON_HDR2X5_1.27MM: CONN HDR SHRD 2X5 MALE 1.27MM TH; ManufacturerPn1: CNC 3220-10-0100-00; Mfg1MrvlAvl: 0; Mfg2MrvlAvl: 0; Mfg3MrvlAvl: 0; ObsoletedByPartID: 0; Part Number: 5044-001-002373; Part Type: CONN; SourceLibrary: PARTS.OLB
J1 = CON_FCI_USB-MICRO-AB_SMD: CONN USB2.0 TYPE MICRO-AB RCPT 5PIN RA HORZ SMD; Files: https://itapps.marvell.com/ACES/User/ServeFile.ashx?PartFileID=8; ManufacturerPn1: FCI 10104111-0001LF; ManufacturerPn2: HIROSE ZX62-AB-5PA(11); Mfg1MrvlAvl: 0; Mfg2MrvlAvl: 0; Mfg3MrvlAvl: 0; ObsoletedByPartID: 0; Part Number: 5044-001-002367; Part Type: CONN; PartType: CONN; Part_Number: 5044-001-002367; SourceLibrary: PARTS.OLB
J3 = CON_MOLEX_USB-MINI-B_SMD: CONN USB MINI-B OTG 5PIN RCPT RA HOZ 0.8mm SMD; Files: https://itapps.marvell.com/ACES/User/ServeFile.ashx?PartFileID=8; ManufacturerPn1: Molex 54819-0572; Mfg1MrvlAvl: 0; Mfg2MrvlAvl: 0; Mfg3MrvlAvl: 0; ObsoletedByPartID: 0; Part Number: 5044-001-002322; Part Type: CONN; PartType: CONN; Part_Number: 5044-001-002322; SourceLibrary: PARTS.OLB
Q1 Q2 = TRANS_DIOD_N-MFET_SOT23-3: TRANS N-CHAN MOSFET 60V(DS) 380MA(ID) SOT23-3; Files: https://itapps.marvell.com/ACES/User/ServeFile.ashx?PartFileID=8; ManufacturerPn1: DIODES 2N7002K-7; Mfg1MrvlAvl: 0; Mfg2MrvlAvl: 0; Mfg3MrvlAvl: 0; ObsoletedByPartID: 0; Part Number: 5044-001-002366; Part Type: IC; PartType: IC; Part_Number: 5044-001-002366; SourceLibrary: PARTS.OLB
R1 R6 R38-R40 R62 R66 = RES: RES THICK FILM 330 OHM 1/16W 5%  0402 SMD; Files: https://itapps.marvell.com/ACES/User/ServeFile.ashx?PartFileID=8; ManufacturerPn1: Cyntec PFR05S-331-JNH; ManufacturerPn2: Walsin WR04X331 JTL; ManufacturerPn3: Yageo RC0402JR-07330RL; Mfg1MrvlAvl: 0; Mfg2MrvlAvl: 0; Mfg3MrvlAvl: 0; ObsoletedByPartID: 0; OneKkPerMoPriceTarget: 0.00020; Part Number: 5044-001-001354; Part_Number: 5044-001-001354; ProtoPriceTargetPerUnit: 0.00150; SourceLibrary: PARTS.OLB
R7 = RES: RES THICK FILM 47K OHM 1/16W 5%  0402 SMD; Files: https://itapps.marvell.com/ACES/User/ServeFile.ashx?PartFileID=8; ManufacturerPn1: Cyntec PFR05S-473-JNH; ManufacturerPn2: Walsin WR04X473 JTL; ManufacturerPn3: Yageo RC0402JR-0747KL; Mfg1MrvlAvl: 0; Mfg2MrvlAvl: 0; Mfg3MrvlAvl: 0; ObsoletedByPartID: 0; OneKkPerMoPriceTarget: 0.00020; Part Number: 5044-001-001406; Part_Number: 5044-001-001406; ProtoPriceTargetPerUnit: 0.00150; SourceLibrary: PARTS.OLB
R2 R3 R9 R16 R19 R20 R26 R29 R35 R37 R51 = RES: RES THICK FILM 10K OHM 1/16W 5%  0402 SMD; ManufacturerPn1: Cyntec PFR05S-103-JNH; ManufacturerPn2: Walsin WR04X103 JTL; ManufacturerPn3: Yageo RC0402JR-0710KL; Mfg1MrvlAvl: 0; Mfg2MrvlAvl: 0; Mfg3MrvlAvl: 0; ObsoletedByPartID: 0; OneKkPerMoPriceTarget: 0.00020; Part Number: 5044-001-001390; ProtoPriceTargetPerUnit: 0.00150; SourceLibrary: PARTS.OLB
R15 R34 = RES: RES THICK FILM 100 OHM 1/16W 5%  0402 SMD; Files: https://itapps.marvell.com/ACES/User/ServeFile.ashx?PartFileID=8; ManufacturerPn1: Cyntec PFR05S-101-JNH; ManufacturerPn2: Walsin WR04X101 JTL; ManufacturerPn3: Yageo RC0402JR-07100RL; Mfg1MrvlAvl: 0; Mfg2MrvlAvl: 0; Mfg3MrvlAvl: 0; ObsoletedByPartID: 0; OneKkPerMoPriceTarget: 0.00020; Part Number: 5044-001-001342; Part_Number: 5044-001-001342; ProtoPriceTargetPerUnit: 0.00150; SourceLibrary: PARTS.OLB
R50 = RES: RES THICK FILM 470 OHM 1/16W 5%  0402 SMD; Files: https://itapps.marvell.com/ACES/User/ServeFile.ashx?PartFileID=8; ManufacturerPn1: Cyntec PFR05S-471-JNH; ManufacturerPn2: Walsin WR04X471 JTL; ManufacturerPn3: Yageo RC0402JR-07470RL; Mfg1MrvlAvl: 0; Mfg2MrvlAvl: 0; Mfg3MrvlAvl: 0; ObsoletedByPartID: 0; OneKkPerMoPriceTarget: 0.00020; Part Number: 5044-001-001358; Part_Number: 5044-001-001358; ProtoPriceTargetPerUnit: 0.00150; SourceLibrary: PARTS.OLB
R52 = RES: RES THICK FILM 1.5K OHM 1/16W 5%  0402 SMD; Files: https://itapps.marvell.com/ACES/User/ServeFile.ashx?PartFileID=8; ManufacturerPn1: Cyntec PFR05S-152-JNH; ManufacturerPn2: Walsin WR04X152 JTL; ManufacturerPn3: Yageo RC0402JR-071K5L; Mfg1MrvlAvl: 0; Mfg2MrvlAvl: 0; Mfg3MrvlAvl: 0; ObsoletedByPartID: 0; OneKkPerMoPriceTarget: 0.00020; Part Number: 5044-001-001370; Part_Number: 5044-001-001370; ProtoPriceTargetPerUnit: 0.00150; SourceLibrary: PARTS.OLB
R72 R74 R85-R87 = RES: RES THICK FILM 2.2K OHM 1/16W 5%  0402 SMD; Files: https://itapps.marvell.com/ACES/User/ServeFile.ashx?PartFileID=8; ManufacturerPn1: Cyntec PFR05S-222-JNH; ManufacturerPn2: Walsin WR04X222 JTL; ManufacturerPn3: Yageo RC0402JR-072K2L; Mfg1MrvlAvl: 0; Mfg2MrvlAvl: 0; Mfg3MrvlAvl: 0; ObsoletedByPartID: 0; OneKkPerMoPriceTarget: 0.00020; Part Number: 5044-001-001374; Part_Number: 5044-001-001374; ProtoPriceTargetPerUnit: 0.00150; SourceLibrary: PARTS.OLB
R101-R104 = RES: RES THICK FILM 0 OHM 1/16W 5% 0402 SMD; ManufacturerPn1: Cyntec PFR05S-000-XNH; ManufacturerPn2: Walsin WR04X000 PTL; ManufacturerPn3: Yageo RC0402JR-070RL; Mfg1MrvlAvl: 0; Mfg2MrvlAvl: 0; Mfg3MrvlAvl: 0; ObsoletedByPartID: 0; OneKkPerMoPriceTarget: 0.00020; Part Number: 5044-001-001293; ProtoPriceTargetPerUnit: 0.00150; SourceLibrary: PARTS.OLB
U3 = IC_TI_LM3526-L_SOIC8: IC USB DUAL PORT PWR SWT 2.7V-5.5V SOIC-8; Files: https://itapps.marvell.com/ACES/User/ServeFile.ashx?PartFileID=8; ManufacturerPn1: TI  LM3526MX-L/NOPB; Mfg1MrvlAvl: 0; Mfg2MrvlAvl: 0; Mfg3MrvlAvl: 0; ObsoletedByPartID: 0; Part Number: 5044-001-002371; Part Type: IC; PartType: IC; Part_Number: 5044-001-002371; SourceLibrary: PARTS.OLB
U5 = IC_FTDI_FT2232D_LQFP48L: IC USB TO SERIAL UART DUAL 4.35V-5.25V LQFP-48L 0.5mm 7x7x1.6mm; Files: https://itapps.marvell.com/ACES/User/ServeFile.ashx?PartFileID=8; ManufacturerPn1: FTDI FT2232D-REEL; Mfg1MrvlAvl: 0; Mfg2MrvlAvl: 0; Mfg3MrvlAvl: 0; ObsoletedByPartID: 0; Part Number: 5044-001-002369; Part Type: IC; PartType: IC; Part_Number: 5044-001-002369; SourceLibrary: PARTS.OLB
U6 U7 = IC_BUFF_TI_1G125_SC70-5: IC SNGL BUFF 3-STATE 1.65V-5.5V SC70-5; Files: https://itapps.marvell.com/ACES/User/ServeFile.ashx?PartFileID=8; ManufacturerPn1: TI SN74LVC1G125DCK; Mfg1MrvlAvl: 0; Mfg2MrvlAvl: 0; Mfg3MrvlAvl: 0; ObsoletedByPartID: 0; Part Number: 5044-001-001980; Part Type: IC; PartType: IC; Part_Number: 5044-001-001980; SourceLibrary: PARTS.OLB
U10 = IC_NXP_IP4220CZ6_TSOP6: IC USB 2.0 DUAL ESD 5.5V MAX TSOP-6 2.9x1.5x1mm; Files: https://itapps.marvell.com/ACES/User/ServeFile.ashx?PartFileID=8; ManufacturerPn1: NXP IP4220CZ6; Mfg1MrvlAvl: 0; Mfg2MrvlAvl: 0; Mfg3MrvlAvl: 0; ObsoletedByPartID: 0; Part Number: 5044-001-002370; Part Type: IC; PartType: IC; Part_Number: 5044-001-002370; SourceLibrary: PARTS.OLB
U12 = IC_IFX_APN337S3959_USON8: IC IPOD AUTHENTICATION COPROCESSOR 2.0C PG-SON-8-1 2.5x2.5x0.6mm; Files: https://itapps.marvell.com/ACES/User/ServeFile.ashx?PartFileID=8; ManufacturerPn1: INFINEON APN 337S3959; Mfg1MrvlAvl: 0; Mfg2MrvlAvl: 0; Mfg3MrvlAvl: 0; Notes: This is APPLE specific part, not available in market. .; ObsoletedByPartID: 0; Part Number: 5044-001-002437; Part Type: IC; PartType: IC; Part_Number: 5044-001-002437; SourceLibrary: PARTS.OLB
U14 = IC_APPLE_MFi343S00177_XDFN8: IC APPLE AUTHENTICATION COPROCESSOR 3.0 XDFN-8 3x2x0.4mm; ManufacturerPn1: APPLE MFi343S00177; Mfg1MrvlAvl: 0; Mfg2MrvlAvl: 0; Mfg3MrvlAvl: 0; Notes: APPLE specific part, not available in market.; ObsoletedByPartID: 0; Part Number: 5044-001-002917; Part Type: IC; SourceLibrary: PARTS.OLB
Y1 = XTAL_TXC_SMD2_12.5X4.8MM: XTAL 6MHz +/-30ppm FUND 8.5pF 120OHM / -40C/+85C SMD-2 12.5X4.8X3.8mm; Files: https://itapps.marvell.com/ACES/User/ServeFile.ashx?PartFileID=8; ManufacturerPn1: TXC AT-6.000MAGB-T; Mfg1MrvlAvl: 0; Mfg2MrvlAvl: 0; Mfg3MrvlAvl: 0; ObsoletedByPartID: 0; Part Number: 5044-001-002355; Part Type: XTAL/OSC; PartType: XTAL/OSC; Part_Number: 5044-001-002355; SourceLibrary: PARTS.OLB
D7 = DIODE_LED_YELLOW: LED YELLOW CLEAR SMD 1.6x0.8x0.55mm; Files: https://itapps.marvell.com/ACES/User/ServeFile.ashx?PartFileID=8; ManufacturerPn1: LITE-ON LTST-C191KSKT; Mfg1MrvlAvl: 0; Mfg2MrvlAvl: 0; Mfg3MrvlAvl: 0; ObsoletedByPartID: 0; Part Number: 5044-001-002443; Part Type: PASSIVE; PartType: PASSIVE; Part_Number: 5044-001-002443; SourceLibrary: PARTS.OLB
D8 = DIODE_LED_AMBER: LED AMBER CLEAR SMD 1.6x0.8x0.8mm; Files: https://itapps.marvell.com/ACES/User/ServeFile.ashx?PartFileID=8; ManufacturerPn1: LITE-ON LTST-C190AKT; Mfg1MrvlAvl: 0; Mfg2MrvlAvl: 0; Mfg3MrvlAvl: 0; ObsoletedByPartID: 0; Part Number: 5044-001-002442; Part Type: PASSIVE; PartType: PASSIVE; Part_Number: 5044-001-002442; SourceLibrary: PARTS.OLB
FD1 FD2 = FIDUCIAL: FIDUCIAL  40 MIL PAD / 80 MIL SOLDER MASK OPENING; Files: https://itapps.marvell.com/ACES/User/ServeFile.ashx?PartFileID=8; ManufacturerPn1: FIDUCIAL_40MP-80MMASK; ManufacturerPn2: NA; ManufacturerPn3: NA; Mfg1MrvlAvl: 0; Mfg2MrvlAvl: 0; Mfg3MrvlAvl: 0; ObsoletedByPartID: 0; OneHundredKPerMoPriceTarget: 0; OneKkPerMoPriceTarget: 0; PartType: MECH; Part_Number: FIDUCIAL_40MPAD80MMMASK; ProtoPriceTargetPerUnit: 0; SourceLibrary: PARTS.OLB
HD2 HD4 = HDR2x16_2MM: HDR 2x16 MALE 0.5MM SQ PINS, 2MM GOLD TH; ManufacturerPn1: MOLEX 0877583216; Mfg1MrvlAvl: 0; Mfg2MrvlAvl: 0; Mfg3MrvlAvl: 0; ObsoletedByPartID: 0; Part Number: 5044-001-002368; Part Type: CONN; SourceLibrary: PARTS.OLB
PCB1-PCB4 = MOUNTING_HOLE: MRVL MOUNTING HOLE SIZE 125 MIL PTH THRU; Files: https://itapps.marvell.com/ACES/User/ServeFile.ashx?PartFileID=8; ManufacturerPn1: MRVL MH125MIL_PTH; Mfg1MrvlAvl: 0; Mfg2MrvlAvl: 0; Mfg3MrvlAvl: 0; ObsoletedByPartID: 0; OneHundredKPerMoPriceTarget: 0; OneKkPerMoPriceTarget: 0; PartType: PCB; Part_Number: MH125MIL_PTH; ProtoPriceTargetPerUnit: 0; SourceLibrary: PARTS.OLB
R58 = RES: RES THICK FILM 1K OHM 1/16W 5%  0402 SMD; Files: https://itapps.marvell.com/ACES/User/ServeFile.ashx?PartFileID=8; ManufacturerPn1: Cyntec PFR05S-102-JNH; ManufacturerPn2: Walsin WR04X102 JTL; ManufacturerPn3: Yageo RC0402JR-071KL; Mfg1MrvlAvl: 0; Mfg2MrvlAvl: 0; Mfg3MrvlAvl: 0; ObsoletedByPartID: 0; OneKkPerMoPriceTarget: 0.00020; Part Number: 5044-001-001366; Part_Number: 5044-001-001366; ProtoPriceTargetPerUnit: 0.00150; SourceLibrary: PARTS.OLB
R61 R89 = RES: RES THICK FILM 1.8K OHM 1/16W 5%  0402 SMD; ManufacturerPn1: Cyntec PFR05S-182-JNH; ManufacturerPn2: Walsin WR04X182 JTL; ManufacturerPn3: Yageo RC0402JR-071K8L; Mfg1MrvlAvl: 0; Mfg2MrvlAvl: 0; Mfg3MrvlAvl: 0; ObsoletedByPartID: 0; OneKkPerMoPriceTarget: 0.00020; Part Number: 5044-001-001372; ProtoPriceTargetPerUnit: 0.00150; SourceLibrary: PARTS.OLB
R77 R83 = RES: RES THICK FILM 2.2K OHM 1/16W 5%  0402 SMD; Files: https://itapps.marvell.com/ACES/User/ServeFile.ashx?PartFileID=8; ManufacturerPn1: Cyntec PFR05S-222-JNH; ManufacturerPn2: Walsin WR04X222 JTL; ManufacturerPn3: Yageo RC0402JR-072K2L; Mfg1MrvlAvl: 0; Mfg2MrvlAvl: 0; Mfg3MrvlAvl: 0; ObsoletedByPartID: 0; OneHundredKPerMoPriceTarget: 0; OneKkPerMoPriceTarget: 0; Part_Number: 5044-001-001374; ProtoPriceTargetPerUnit: 0; SourceLibrary: PARTS.OLB
S1 = SW_ESW_TL3302_SPST: SWITCH TACT SPST GULL WING 50mA 12V SMD2 10.2x3.5x5.0mm; Files: https://itapps.marvell.com/ACES/User/ServeFile.ashx?PartFileID=8; ManufacturerPn1: E-Switch TL3302BF130QG; Mfg1MrvlAvl: 0; Mfg2MrvlAvl: 0; Mfg3MrvlAvl: 0; ObsoletedByPartID: 0; Part Number: 5044-001-002302; Part Type: ELEC-MECH; PartType: ELEC-MECH; Part_Number: 5044-001-002302; SourceLibrary: PARTS.OLB
SW1 SW2 SW4 SW5 = SW_PAN_SMD4: SWITCH SPST S-P-TRAVEL 0.25mm J-BENT 1.3NF 6.5x6.0x3.1mm; Filename: <Filename>; Files: https://itapps.marvell.com/ACES/User/ServeFile.ashx?PartFileID=8; ManufacturerPn1: PANASONIC EVQ-Q2K03W; Mfg1MrvlAvl: 0; Mfg2MrvlAvl: 0; Mfg3MrvlAvl: 0; ObsoletedByPartID: 0; Part Number: 5044-001-002259; Part Type: ELEC-MECH; PartType: ELEC-MECH; Part_Number: 5044-001-002259; SourceLibrary: PARTS.OLB
TP1 TP5 = TESTLOOP: TP PC MULTI PURPOSE 0.125IN BLK TH; Files: https://itapps.marvell.com/ACES/User/ServeFile.ashx?PartFileID=8; ManufacturerPn1: KEYSTONE 5011; Mfg1MrvlAvl: 0; Mfg2MrvlAvl: 0; Mfg3MrvlAvl: 0; ObsoletedByPartID: 0; Part Number: 5044-001-002238; Part Type: MECH; PartType: MECH; Part_Number: 5044-001-002238; SourceLibrary: PARTS.OLB
Y2 = XOSC_TXC_3.2X2.5MM: XOSC 32.768 KHZ 3.3V +/-25ppm 15pF -10C/+70C SMD 3.2x2.5x1.0mm; Files: https://itapps.marvell.com/ACES/User/ServeFile.ashx?PartFileID=8; ManufacturerPn1: TXC 7XZ-32.768KBA-T; Mfg1MrvlAvl: 0; Mfg2MrvlAvl: 0; Mfg3MrvlAvl: 0; ObsoletedByPartID: 0; Part Number: 5044-001-002357; Part Type: XTAL/OSC; PartType: XTAL/OSC; Part_Number: 5044-001-002357; SourceLibrary: PARTS.OLB

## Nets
+3.3V_FTDI: C6.2 C7.1 C8.1 C15.1 C16.1 C20.1 C21.1 JP3.2 R38.2 R39.2 R40.2 U5.10(SI/WUA) U5.14(VCCI-OA) U5.26(SI/WUB) U5.31(VCCI-OB) U6.5(VCC) U7.5(VCC)
+3.3V_LDO: C3.2 C19.1 C22.1 C35.1 C36.1 D7.1(ANODE) D8.1(ANODE) HD1.1 HD2.1 HD2.31 HD4.1 HD4.2 JP3.1 R1.2 R2.2 R3.2 R6.1 R9.1 R16.1 R20.1 R26.2 R29.1 R35.1 R37.1 R58.1 R75.1 R77.1 R78.1 R81.1 R83.1 R85.1 R86.1 R87.1 TP4.1 U11.5(VOUT) U12.8(VCC) U14.8(VCC) Y2.4(VDD)
+3.3V_Module: JP8.2 TP3.1 U4.10(3.3V) U4.11(3.3V) U4.12(3.3V)
+5V_EXT: C29.1 C31.1 J2.1 JP7.3
+5V_FTDI: C9.1 C10.1 C14.1 JP6.2 R50.1 R51.1 U5.3(VCC) U5.42(VCC)
+5V_SYS: C5.2 D9.1(ANODE) HD2.23 HD2.25 HD4.16 HD4.18 JP4.3 JP5.1 JP6.1 JP7.2 TP2.1 U3.7(IN)
+5V_USB: C25.2 C26.2 J3.1(VBUS) JP7.1
GND: C1.1 C2.1 C3.1 C4.2 C5.1 C6.1 C7.2 C8.2 C9.2 C10.2 C11.1 C12.2 C13.1 C14.2 C15.2 C16.2 C17.2 C18.2 C19.2 C20.2 C21.2 C22.2 C23.2 C25.1 C26.1 C29.2 C31.2 C32.2 C33.2 C34.2 C35.2 C36.2 HD1.3 HD1.5 HD1.7 HD1.9 HD2.2 HD2.7 HD2.9 HD2.12 HD2.13 HD2.15 HD2.17 HD2.19 HD2.21 HD2.27 HD2.29 HD3.2 HD4.3 HD4.4 HD4.6 HD4.8 HD4.10 HD4.12 HD4.13 HD4.14 HD4.15 HD4.17 HD4.20 HD4.22 HD4.24 HD4.26 HD4.28 HD4.30 HD4.32 J1.5(GND) J1.6(SHIELD1) J1.7(SHIELD2) J1.8(SHIELD3) J1.9(SHIELD4) J2.2 J2.3 J3.5(GND) J3.6(SHIELD1) J3.7(SHIELD2) J3.8(SHIELD3) J3.9(SHIELD4) Q1.2(SOURCE) Q2.2(SOURCE) R19.2 R61.2 R76.2 R79.1 R80.2 R82.1 R84.2 R89.2 R92.2 R95.2 R98.2 S1.2 SW1.3(B2) SW1.4(B1) SW2.3(B2) SW2.4(B1) TP1.1 TP5.1 U3.6(GND) U4.1(GND) U4.9(GND) U4.19(GND) U4.26(GND) U4.32(GND) U4.36(GND) U4.44(GND) U4.50(GND) U5.9(GND) U5.18(GND) U5.25(GND) U5.34(GND) U5.45(AGND) U5.47(TEST) U6.3(GND) U7.3(GND) U10.2(GND) U11.2(GND) U12.1(GND) U12.9(EPAD) U13.3(GND) U13.6(GND) U13.7(GND) U14.1(GND) U14.4(GND) U14.7(GND) U14.9(EPAD) Y2.2(GND)
VBUS: C1.2 C2.2 J1.1(VBUS) JP1.2 JP2.2 R7.2 U10.5(VP)
EXT_BATTERY: C23.1 HD3.1 JP4.1
FT_RX_LED: D4.2(CATHODE) U5.28(BCBUS2)
FT_TCK: HD1.4 R19.1 R47.2 U4.46(MCI_TCK)
FT_TDI: HD1.8 R29.2 R46.2 U4.48(MCI_TDI)
FT_TDO: HD1.6 R20.2 R48.2 U4.45(MCI_TDO)
FT_TMS: HD1.2 R9.2 R49.2 U4.47(MCI_TMS)
FT_TRST#: HD1.10 R37.2 R55.2 U4.49(MCI_TRST)
FT_TX_LED: D5.2(CATHODE) U5.27(BCBUS3)
GPIO_0: HD4.5 U4.38(UART0_CTS)
GPIO_1: HD4.7 U4.39(UART0_RTS)
GPIO_2: HD2.22 R42.1 U4.40(UART0_TXD)
GPIO_3: HD2.24 R41.1 U4.41(UART0_RXD)
GPIO_4: HD2.3 R86.2 R101.1 R103.1 U4.42(SDA)
GPIO_5: HD2.5 R85.2 R102.2 R104.1 U4.43(SCL)
GPIO_11: HD2.4 U4.2(UART1_CTS)
GPIO_12: HD2.6 U4.3(UART1_RTS)
GPIO_13: HD2.8 R28.2 R36.2
GPIO_13_M: R36.1 R57.1 U4.4(UART1_TXD)
GPIO_14: HD2.10 R25.2 R57.2
GPIO_14_M: R25.1 R28.1 U4.5(UART1_RXD)
GPIO_16: HD2.26 JP11.1 U4.6(GPIO16)
GPIO_17: HD2.28 U4.7(GPIO17)
GPIO_18: HD2.30 U4.8(GPIO18)
GPIO_22: HD2.11 R71.1 U4.14(WAKE0)
GPIO_23: HD2.20 R73.1 U4.15(WAKE1)
GPIO_24: HD2.32 R4.1 U4.16(PUSH_SW1)
GPIO_25: HD2.16 R59.1 U4.17(32kHz_CLKIN)
GPIO_26: HD2.14 R5.1 U4.18(PUSH_SW0)
GPIO_27: HD4.19 JP10.1 R33.1 U4.25(USB_DRVBUS)
GPIO_34: R14.1 U4.20(USB_PWRFAULT)
GPIO_39: HD2.18 R24.1 U4.27(GPIO39)
GPIO_40: HD4.9 R32.1 U4.28(GPIO40)
GPIO_41: HD4.11 R22.1 U4.29(GPIO41)
GPIO_42: HD4.27 U4.30(GPIO42)
GPIO_43: HD4.29 U4.31(GPIO43)
GPIO_46: HD4.31 U4.33(GPIO46)
GPIO_47: HD4.25 U4.34(GPIO47)
GPIO_48: HD4.21 U4.35(GPIO48)
GPIO_49: HD4.23 U4.37(GPIO49)
I2C0_RST: R24.2 R87.2 U12.7(RST)
I2C0_SCL_MFI2p0C: R102.1 U12.6(SCL)
I2C0_SCL_MFI3p0: R104.2 U14.6(SCL)
I2C0_SDA_MFI2p0C: R101.2 U12.2(SDA)
I2C0_SDA_MFI3p0: R103.2 U14.5(SDA)
JTAG_LED: D3.2(CATHODE) U5.29(BCBUS1)
LED1: R32.2 R66.2
LED2: R22.2 R62.2
M_RTC_XIN: R59.2 Y2.3(OUT)
NC: U12.4(NC)
PUSH_SW0: R3.1 R5.2 SW2.1(A1) SW2.2(A2)
PUSH_SW1: R2.1 R4.2 SW1.1(A1) SW1.2(A2)
RESETn: R56.2 S1.1 U4.13(RESETn)
RSTOUT#: R52.2 U5.5(RSTOUT#)
UART0_RXD: R41.2 U5.40(BDBUS0)
UART0_TXD: R42.2 U5.39(BDBUS1)
USB_DM: J1.2(D-) U4.24(USB_DM) U10.4(IO3)
USB_DM1: J3.2(D-) R54.1
USB_DP: J1.3(D+) U4.23(USB_DP) U10.3(IO2)
USB_DP1: J3.3(D+) R53.1
USB_DRVBUS: R33.2 R34.2
USB_ID: J1.4(ID) U4.22(USB_ID) U10.1(IO1)
USB_OTG_POWER_FAULT: R14.2 R15.2
USB_VBUS: JP2.1 U4.21(USB_VBUS)
WAKEUP0: R71.2 R72.2 SW4.1(A1) SW4.2(A2)
WAKEUP1: R73.2 R74.2 SW5.1(A1) SW5.2(A2)
XTIN: C11.2 U5.43(XTIN) Y1.1
XTOUT: C13.2 U5.44(XTOUT) Y1.2
N15444816: R54.2 U5.8(USBDM)
N15444820: R51.2 U5.4(RESET#)
N15444850: C12.1 R50.2 U5.46(AVCC)
N15444866: C17.1 U5.6(3V3OUT)
N15445084: R52.1 R53.2 U5.7(USBDP)
N15445992: R44.2 R45.2 U5.35(BDBUS5)
N15445996: R44.1 U5.36(BDBUS4)
N15446012: R45.1 U5.33(BDBUS6)
N15446156: R47.1 U5.24(ADBUS0)
N15446160: R46.1 U5.23(ADBUS1)
N15446164: R48.1 U5.22(ADBUS2)
N15446168: R49.1 U5.21(ADBUS3)
N15446278: U5.15(ACBUS0) U7.1(O~{E})
N15446290: U5.13(ACBUS1) U7.2(A)
N15446302: U5.12(ACBUS2) U6.1(O~{E})
N15446318: U5.11(ACBUS3) U6.2(A)
N15497012: R77.2 R80.1 SW4.3(B2) SW4.4(B1)
N15533368: R43.1 U5.38(BDBUS2)
N15533372: R43.2 U5.37(BDBUS3)
N15634236: JP10.2 R61.1
N15687385: R58.2 Y2.1(EC)
N15736610: JP4.2 JP9.2
N15739976: Q2.1(GATE) R27.1 R34.1
N15739980: Q2.3(DRAIN) R26.1 R27.2 U3.1(~{ENA})
N15740382: C4.1 JP1.1 U3.8(OUT_A)
N15740470: R35.2 U3.4(~{ENB})
N15740498: D2.2(CATHODE) R15.1 R16.2 U3.2(FLAG_A)
N15740674: D2.1(ANODE) R6.2
N15740714: Q1.1(GATE) R7.1
N15740752: D1.1(ANODE) R1.1
N15740760: D1.2(CATHODE) Q1.3(DRAIN)
N15746725: R74.1 R81.2 R82.2
N15751310: C18.1 JP5.2 R93.1 U11.1(VIN)
N16196654: R72.1 R78.2 R79.2
N16197908: R83.2 R84.1 SW5.3(B2) SW5.4(B1)
N16205959: R56.1 U6.4(Y)
N16205963: R55.1 U7.4(Y)
N16206930: JP11.2 R89.1
N16236079: D8.2(CATHODE) R66.1
N16236083: D7.2(CATHODE) R62.1
N16236450: D9.2(CATHODE) R92.1
N16270711: D3.1(ANODE) R38.1
N16270723: D4.1(ANODE) R39.1
N16270727: D5.1(ANODE) R40.1
N16280270: R75.2 R76.1 U11.4(ADJ)
N16280632: R93.2 U11.3(~{SHDN})
N16281114: C32.1 JP9.1 R94.1 U13.8(IN)
N16281384: R94.2 U13.5(~{SHDN})
N16282144: C33.1 C34.1 JP8.1 R96.1 R100.1 U13.1(OUT)
N16282599: JP12.3 R98.1 R99.1(A) R99.2(WIPER)
N16282621: JP12.1 R95.1 R96.2
N16283494: JP12.2 U13.2(SENSE/ADJ)
N16284614: R99.3(B) R100.2

Not connected (* = marked no-connect by the designer): FD1 1*; FD2 1*; J3 4(ID)*; PCB1 1*; PCB2 1*; PCB3 1*; PCB4 1*; U3 3(FLAG_B)* 5(OUT_B)*; U5 1(EESK)* 2(EEDATA)* 16(ADBUS7)* 17(ADBUS6)* 19(ADBUS5)* 20(ADBUS4)* 30(BCBUS0)* 32(BDBUS7)* 41(PWREN#)* 48(EECS)*; U10 6(IO4)*; U12 3(NC)* 5(NC)*; U13 4(NC)*; U14 2(NC)* 3(NC)*

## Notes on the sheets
sheet 1
- NXP SEMICONDUCTORS
- Power Distribution
- Block Diagram
- ARM MIPI JTAG
- I2C
- I/O connector 1
- EXT_BATTERY
- JP4
- JP7
- JP9
- +3.3V_Module
- 3.3V LDO
  for Module
- +5V_USB
- +5V_SYS
- USB
  OTG
- OTG Host
  Supply Ckt
- FTDI
  JTAG/
  UART0
- +5V_EXT
- JP8
- JP5
- +3.3V_LDO
- NXP 88MW3xx
  2.4GHz WiFi Module
- 3.3V LDO
- +5V USB
  +5V EXT
- 3.3V
- +3.3V_FTDI
- LDO
- JP6
- JP3
- +5V_FTDI
- Ext
  Battery
- Pushbuttons
- LEDs
- I/O connector 2
- Table of Contents
- _____________________________
- 1. Power Distribution, Block Diagram
  2. Power, Module Interface, Pin Muxing
  3. FTDI- JTAG UART, USB OTG, MCI JTAG, MFi
  4. Sleep Clock, Strap Options, GPIOs on Header
  5. Revision History
- Adapter Board
  AB-88MW3XX V3.0 Schematic
- NOTE: THIS SCHEMATIC IS A PRELIMINARY DESIGN.
  NXP RESERVES THE RIGHT TO MAKE CHANGES
  TO THE SCHEMATIC AT ANY TIME WITHOUT NOTICE.
sheet 2
- Power
- 3.3V LDO for Module
- 3.6k
- 5K POT
- 4.02k 1%
- LED Power Indicator
- External Battery Supply
- 3.3V LDO
- PIN MUXING
- Module Interface
- NOTE: THIS SCHEMATIC IS A PRELIMINARY DESIGN.
  NXP RESERVES THE RIGHT TO MAKE CHANGES
  TO THE SCHEMATIC AT ANY TIME WITHOUT NOTICE.
sheet 3
- FTDI- JTAG UART
- MCI JTAG Connector
- Note: Remove JP3,JP6
  to power off FTDI
- MFi 2.0C and 3.0
- USB OTG
- Apple Auth Coprocessor 2.0C
  337S3959
- Shared pad
- Shared pad
- Apple Auth Coprocessor 3.0
  343S00177
- RED LED
- Note:
  Load R101 and R102 to connect I2C0 lines to MFi2.0C IC( U12)
  Load R103 and R104 to connect I2C0 lines to MFi3.0 IC ( U14)
- R85, R86 = 2.2K when using MFi 2.0C ( U12)
  R85, R86 = 12K when using MFi 3.0 ( U14)
- NOTE: THIS SCHEMATIC IS A PRELIMINARY DESIGN.
  NXP RESERVES THE RIGHT TO MAKE CHANGES
  TO THE SCHEMATIC AT ANY TIME WITHOUT NOTICE.
sheet 4
- Strap Option
- Sleep Clock
- Application LEDs
- STRAP1
- STRAP0
- Boot Options
- Strap 1
  GPIO_16
- Strap 0
  GPIO_27
- Boot From
- 0
- 0
- UART
- 0
- 1
- Reserved
- 1
- 0
- USB
- 1
- 1
- Flash (default)
- 88MW3xx GPIOs Function Table
- GPIOs on HEADER
- Push Buttons
- GPIO #
- Function 0
- Function 1
- Function 2
- GPIO_00
- UART0_CTS
- SSP0_CLK
- GPT0_CH0
- GPT0_CH1
- GPIO_01
- UART0_RTS
- SSP0_FRM
- UART0_TXD
- GPT0_CH2
- RESETn
- GPIO_02
- SSP0_TXD
- GPT0_CH3
- GPIO_03
- UART0_RXD
- SSP0_RXD
- GPIO_04
- I2C0_SDA
- CAN_TX
- GPT0_CH4
- GPIO_05
- I2C0_SCL
- CAN_RX
- GPT0_CH5
- GPIO_11
- UART1_CTS
- SSP1_CLK
- IR_IN
- GPIO_12
- UART1_RTS
- SSP1_FRM
- IR_OUT
- GPIO_13
- UART1_TXD
- SSP1_TXD
- IR_TXM
- WAKE0
- WAKE1
- GPIO_14
- UART1_RXD
- SSP1_RXD
- _
- _
- _
- GPIO_16
- STRAP1
- _
- GPIO_17
- GPT3_CH0
- I2C1_SCL
- GPIO_18
- GPT3_CH1
- I2C1_SDA
- _
- GPIO_22
- WAKE0
- _
- _
- WAKE1
- _
- _
- GPIO_23
- _
- GPIO_24
- PUSH_SW1
- GPT1_CH5
- 32KHz_CLK_IN
- GPIO_25
- I2C1_SDA
- CAN_TX
- GPIO_26
- PUSH_SW0
- I2C1_SCL
- CAN_RX
- _
- GPIO_27
- STRAP0
- USB_DRVBUS
- _
- _
- GPIO_34
- USB_PWR_FAULT
- (NOT ON HEADER)
- GPIO_39
- _
- I2C0_RESET
- IR_IN
- PUSH BUTTON 1
- PUSH BUTTON 2
- GPIO_40
- LED1
- _
- IR_OUT
- LED2
- _
- GPIO_41
- IR_TXM
- ADC0_0
- ACOMP0
- GPIO_42
- VOICE_P
- ADC0_1
- ACOMP1
- GPIO_43
- VOICE_N
- SSP2_CLK
- ADC0_4
- GPIO_46
- UART2_CTS
- GPIO_47
- SSP2_FRM
- UART2_RTS
- ADC0_5
- GPIO_48
- SSP2_TXD
- ADC0_6
- UART2_TXD
- GPIO_49
- SSP2_RXD
- UART2_RXD
- ADC0_7
- NOTE: THIS SCHEMATIC IS A PRELIMINARY DESIGN.
  NXP RESERVES THE RIGHT TO MAKE CHANGES
  TO THE SCHEMATIC AT ANY TIME WITHOUT NOTICE.
sheet 5
- REVISION HISTORY
- Design Version
- Document Revision
- Change List
- Date
- Initial Release
- V 3.0
- Rev 1
- 31-Jul-2020
- NOTE: THIS SCHEMATIC IS A PRELIMINARY DESIGN.
  NXP RESERVES THE RIGHT TO MAKE CHANGES
  TO THE SCHEMATIC AT ANY TIME WITHOUT NOTICE.
